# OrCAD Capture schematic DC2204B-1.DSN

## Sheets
1 PAGE1: size C
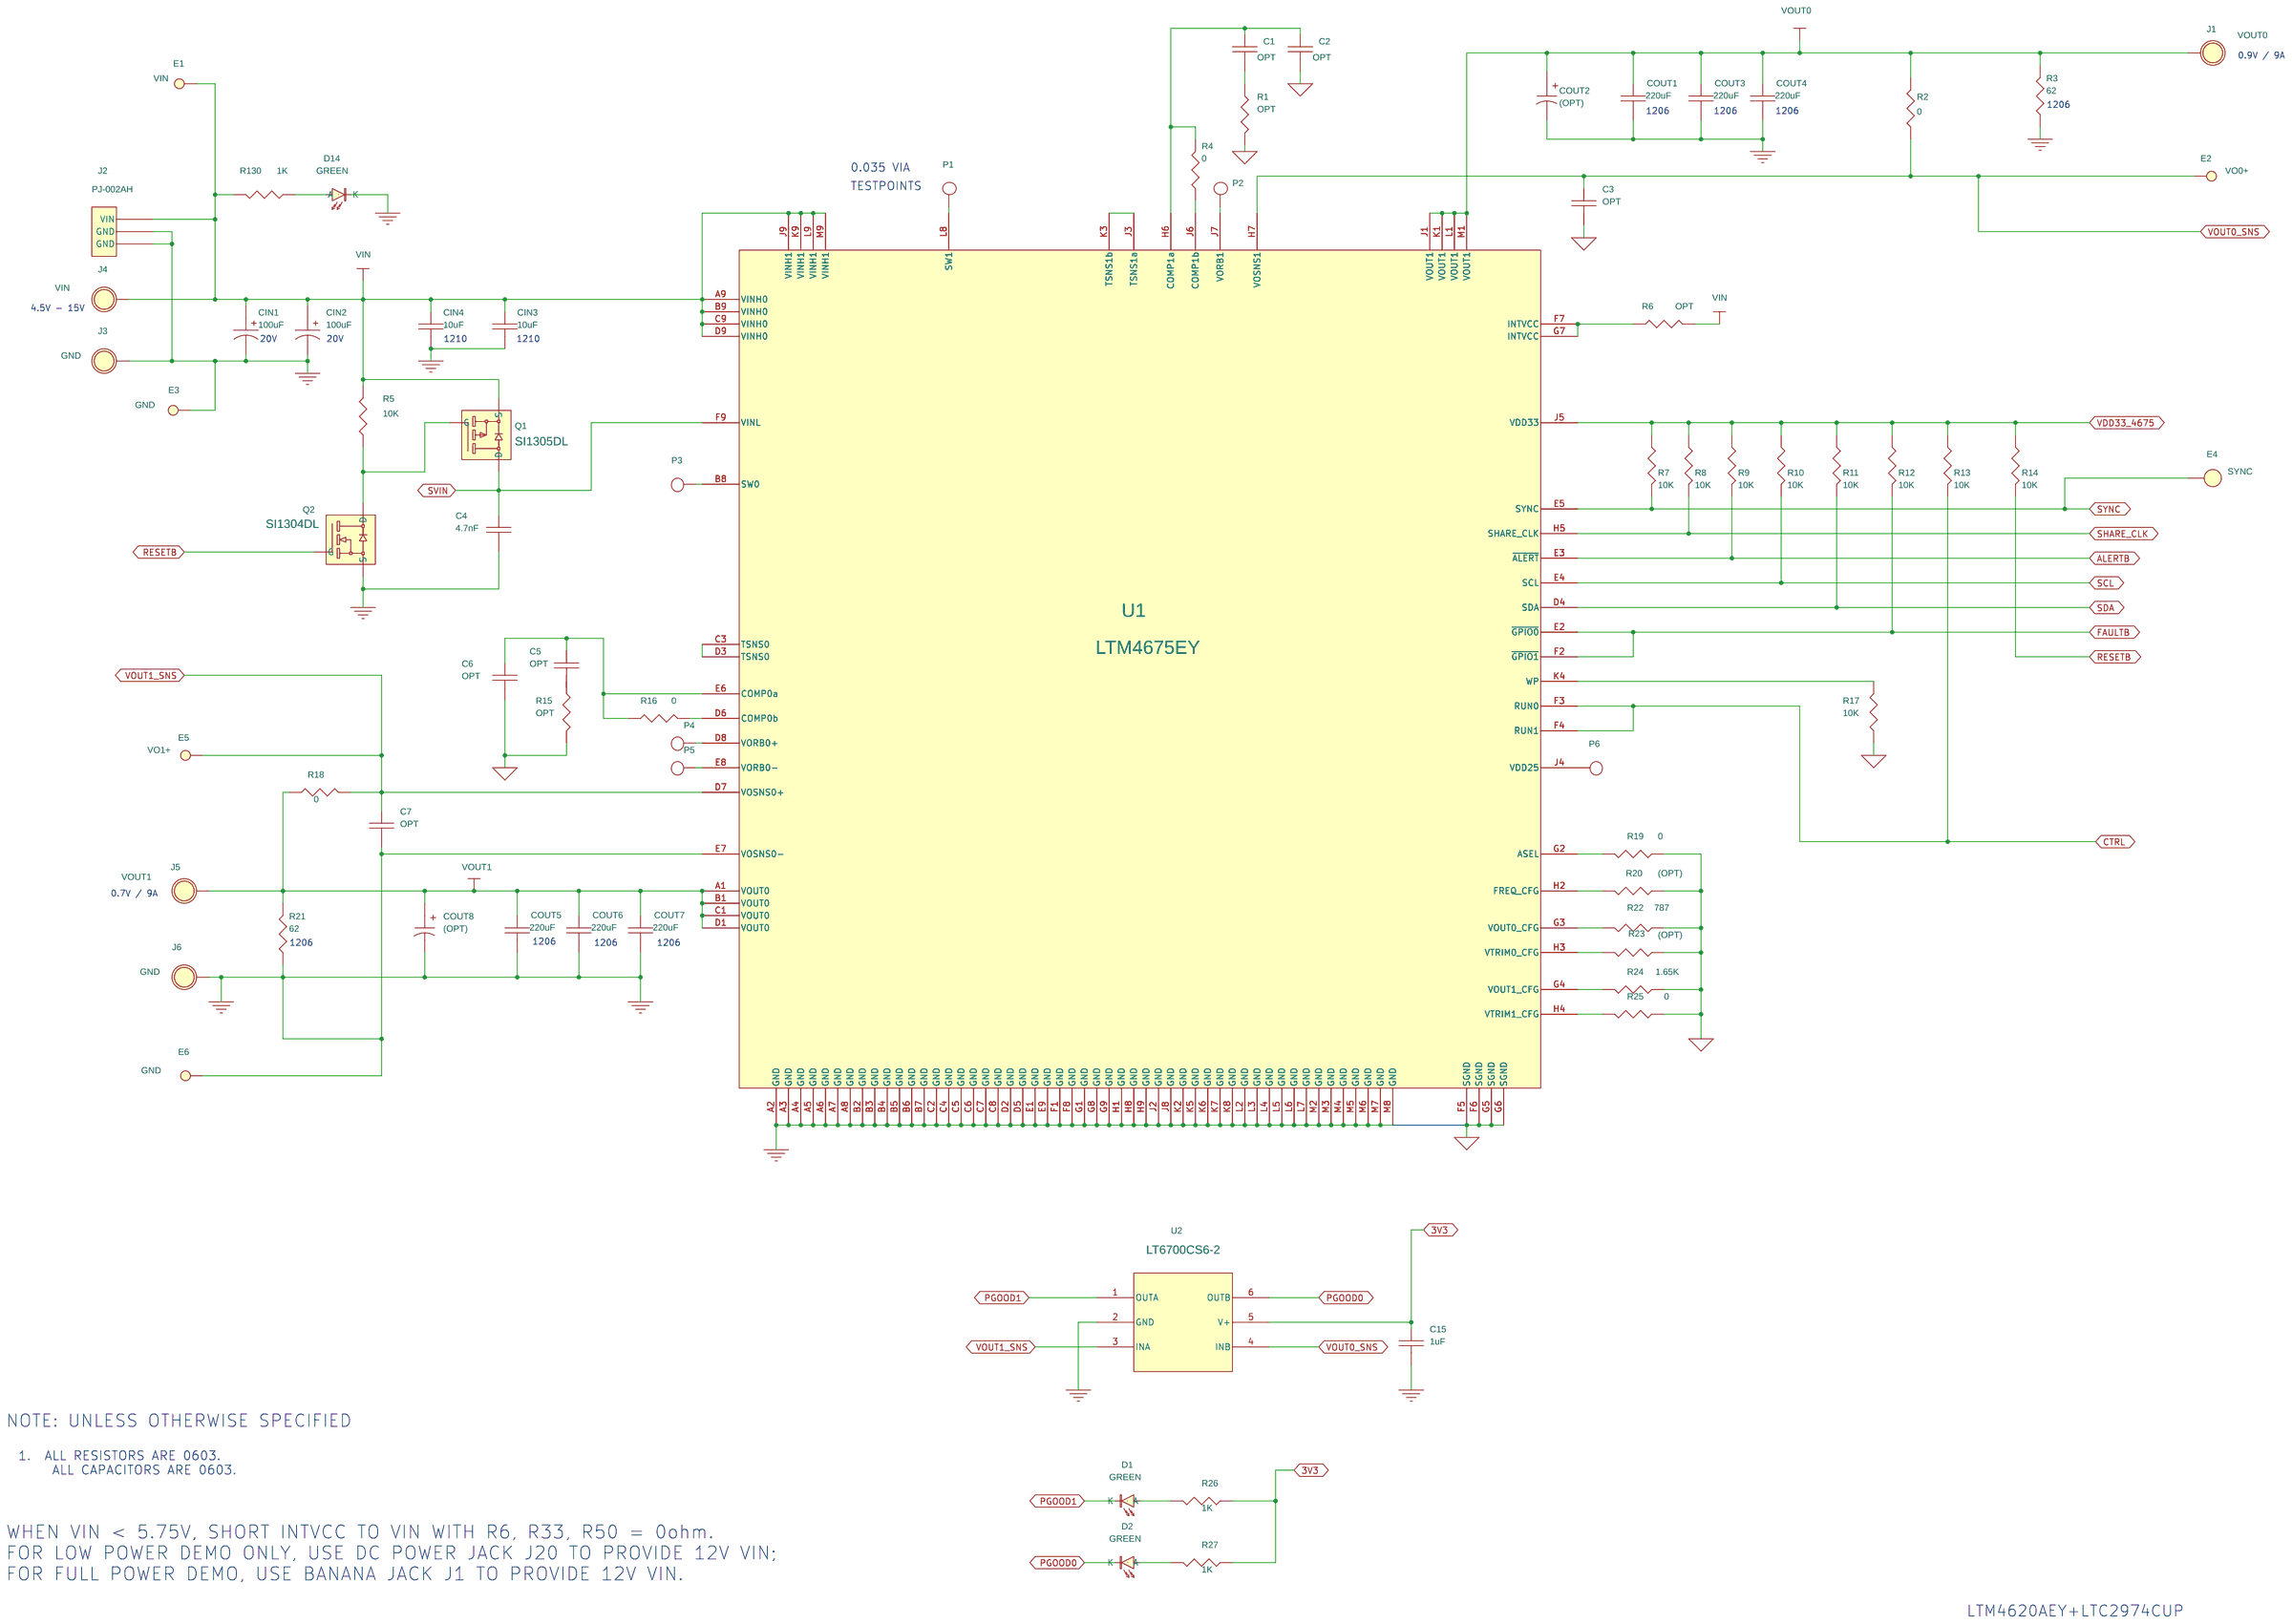
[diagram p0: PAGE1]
2 PAGE2: size C; title: µMODULE POWER STICK WITH POWER SYSTEM MANAGEMENT; rev: 1; company: TM
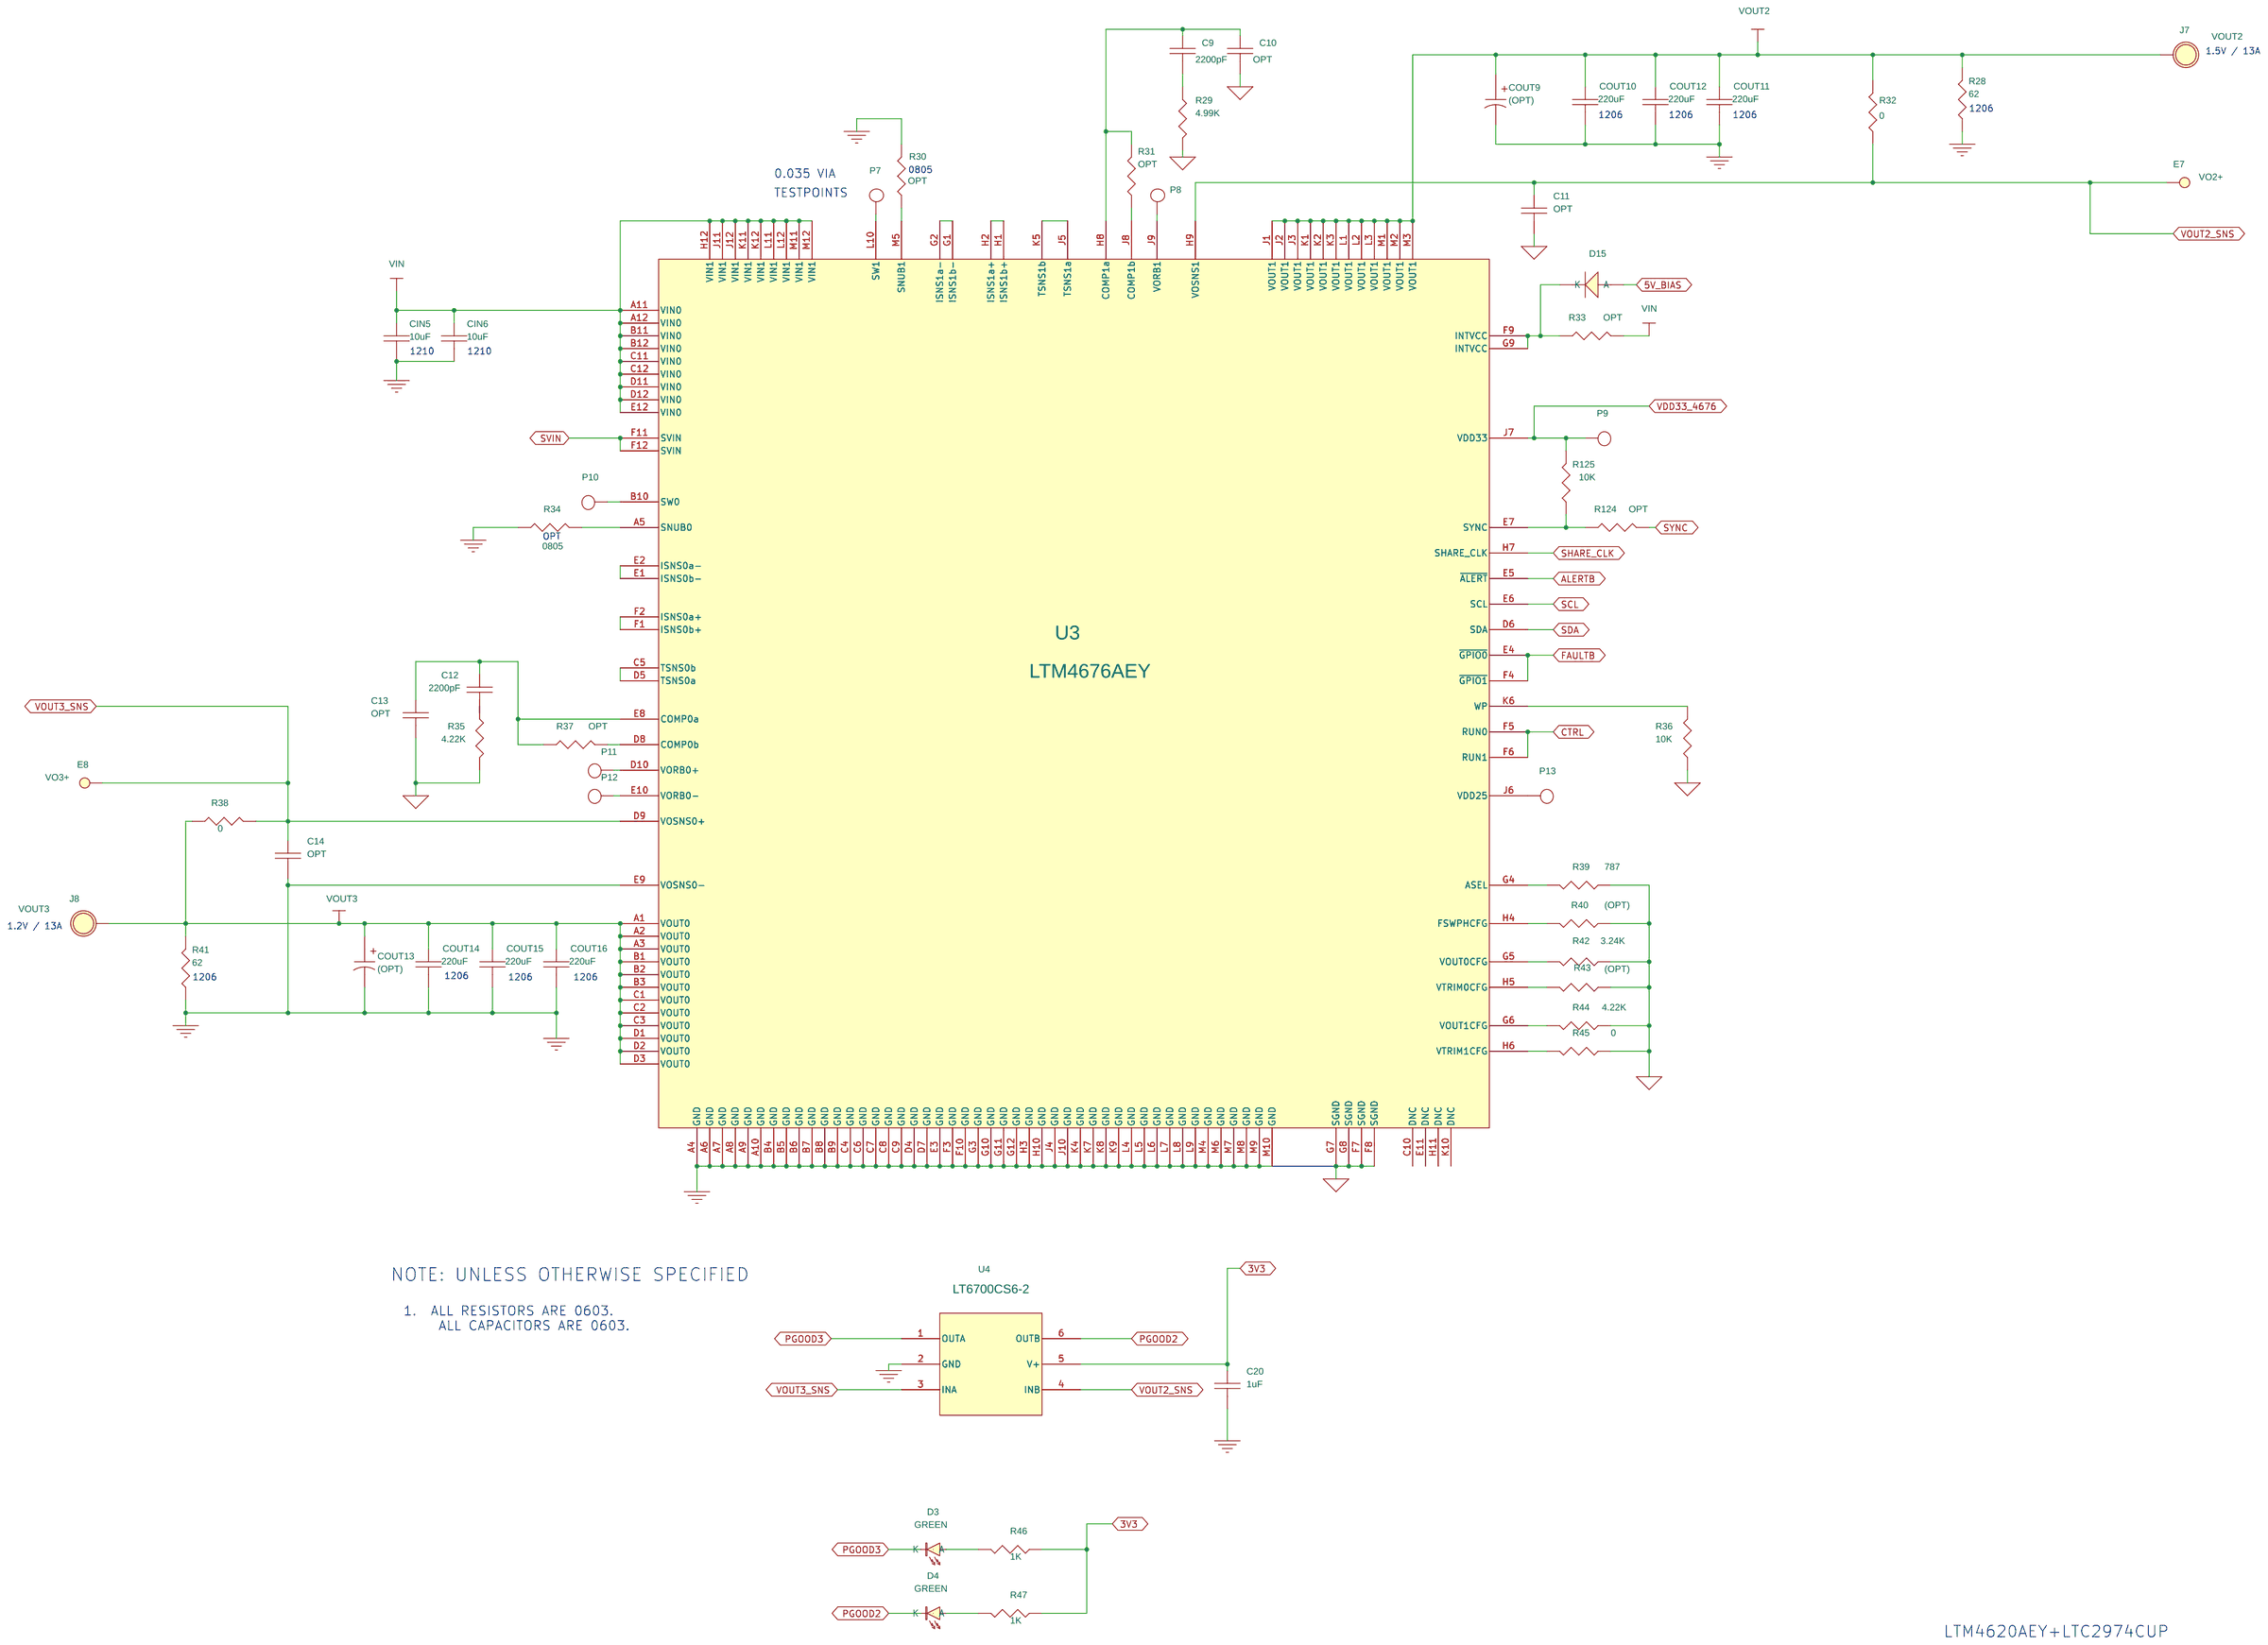
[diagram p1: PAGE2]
3 PAGE3: size C; title: µMODULE POWER STICK WITH POWER SYSTEM MANAGEMENT; rev: 1; company: TM
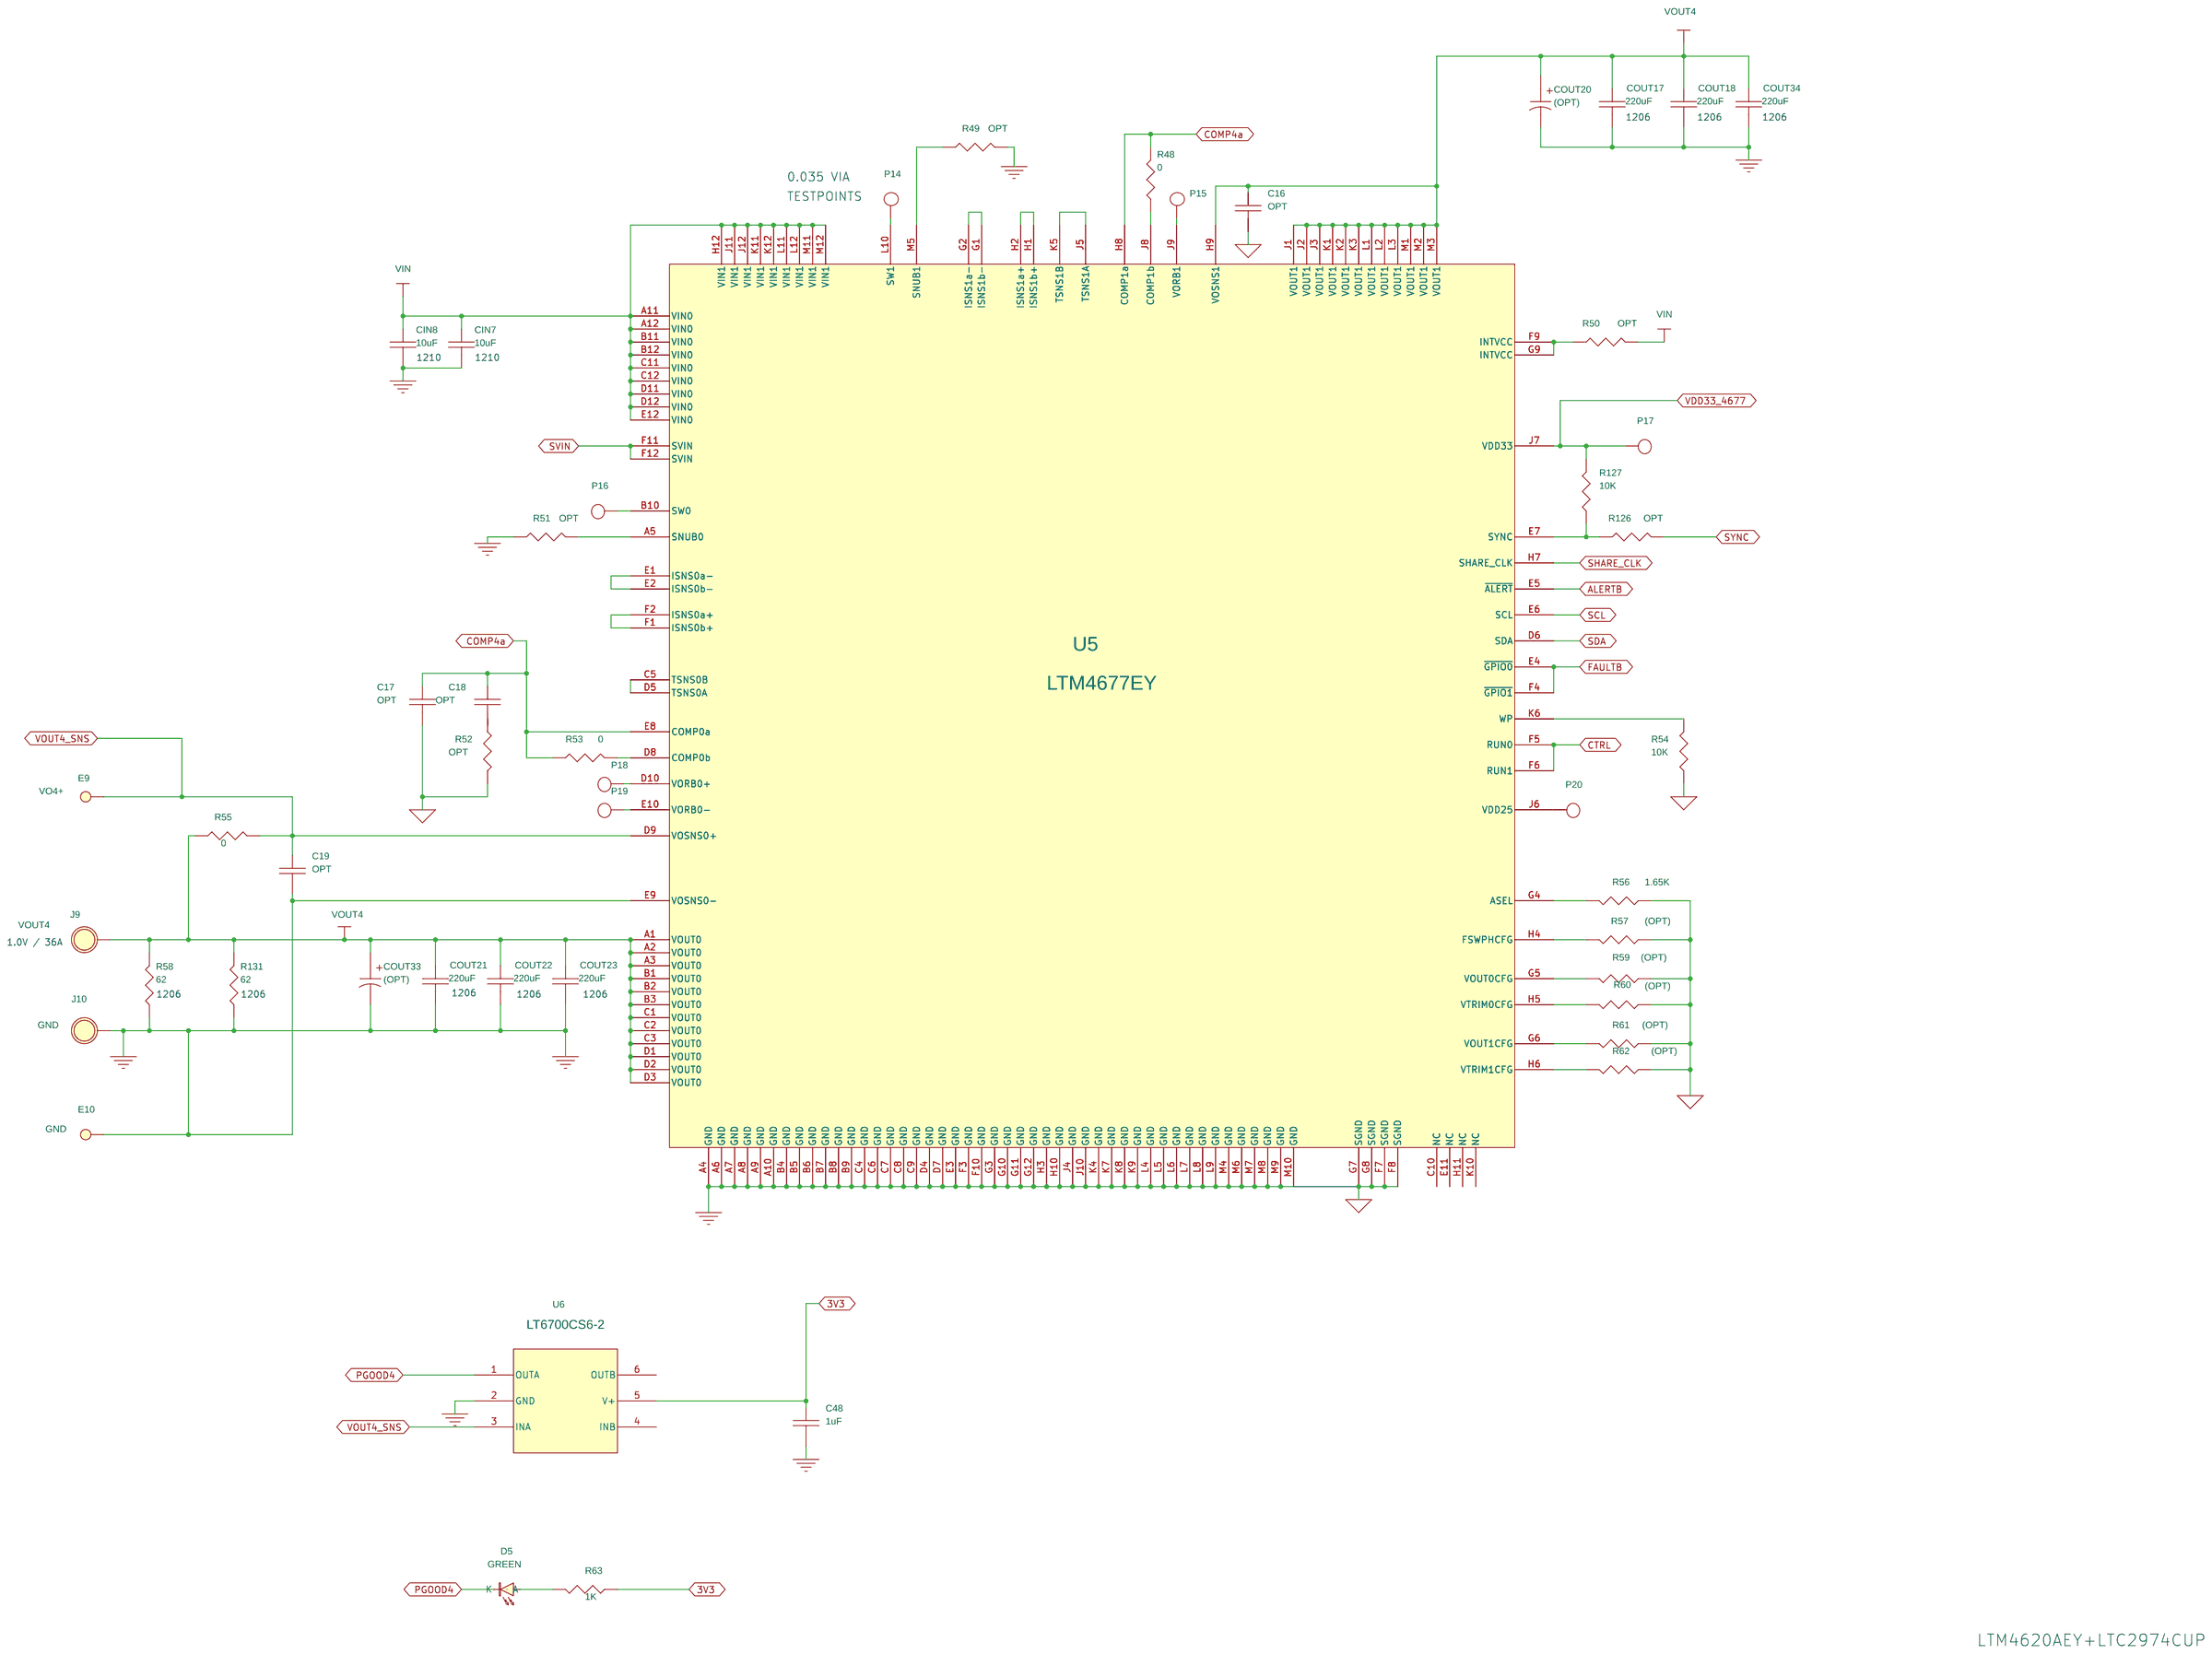
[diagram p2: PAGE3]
4 PAGE4: size Custom; title: µMODULE POWER STICK WITH POWER SYSTEM MANAGEMENT; rev: 1; company: TM
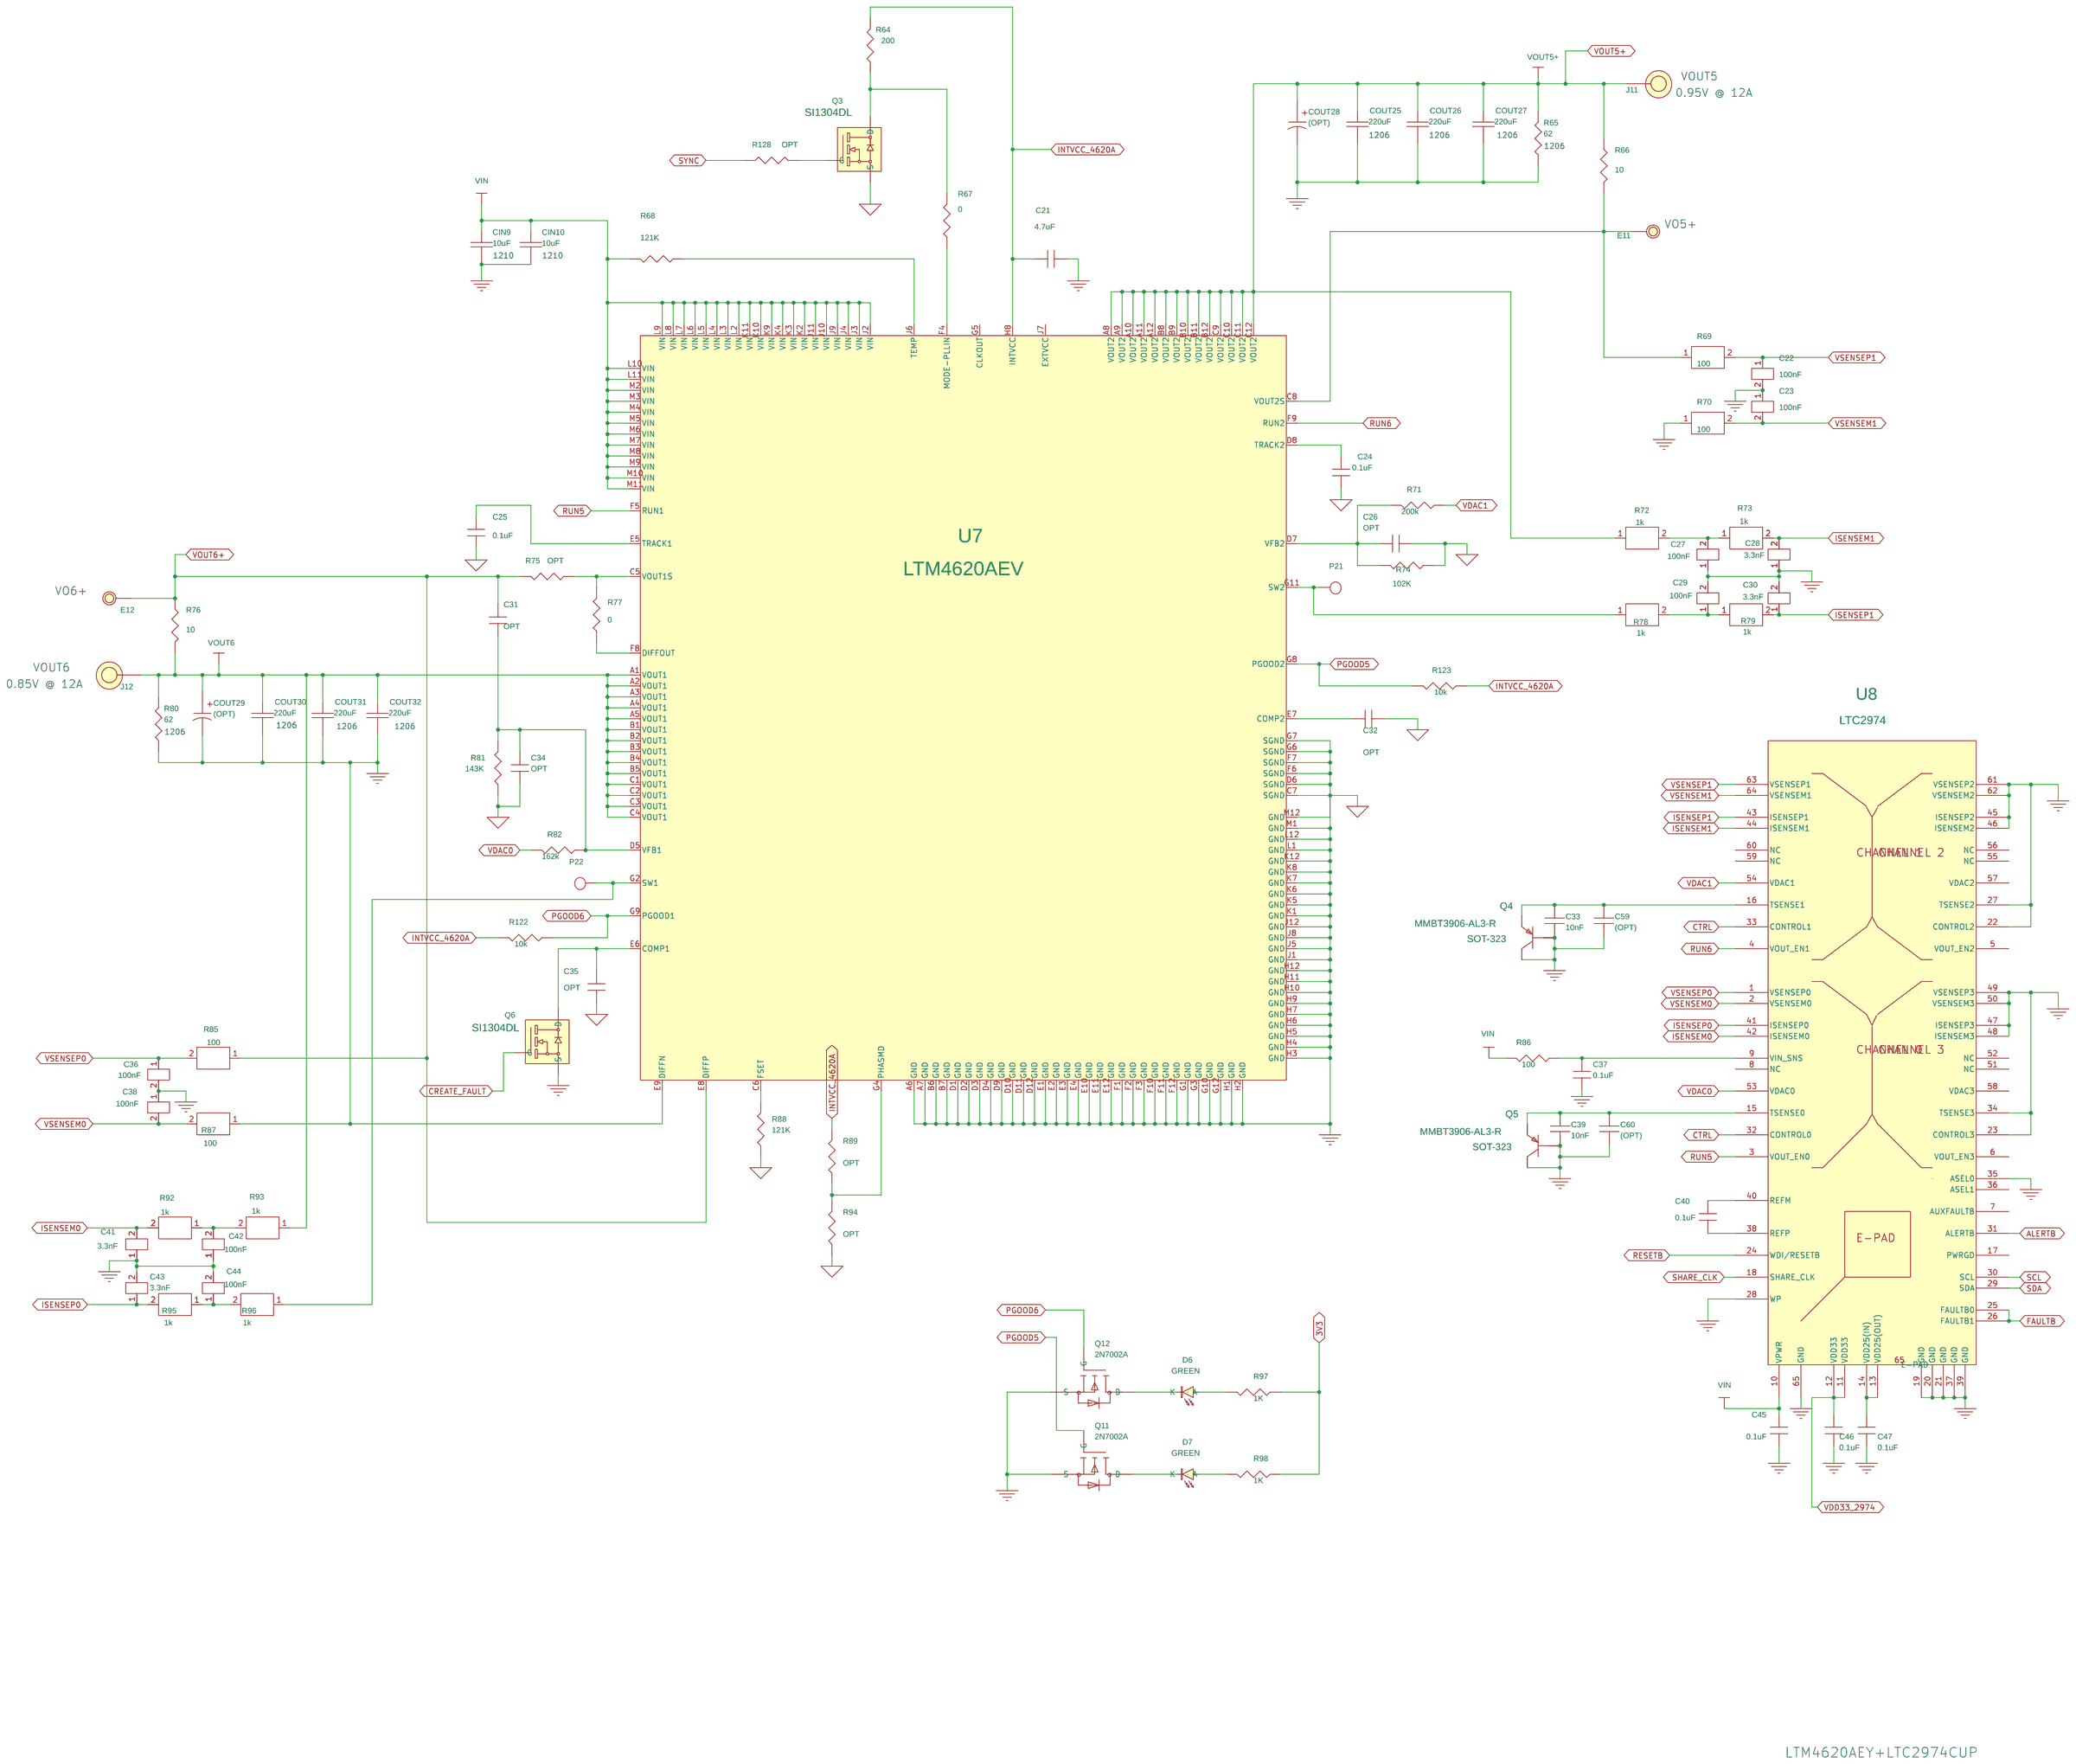
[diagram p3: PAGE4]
5 PAGE5: size C; title: µMODULE POWER STICK WITH POWER SYSTEM MANAGEMENT; rev: 1; company: TM
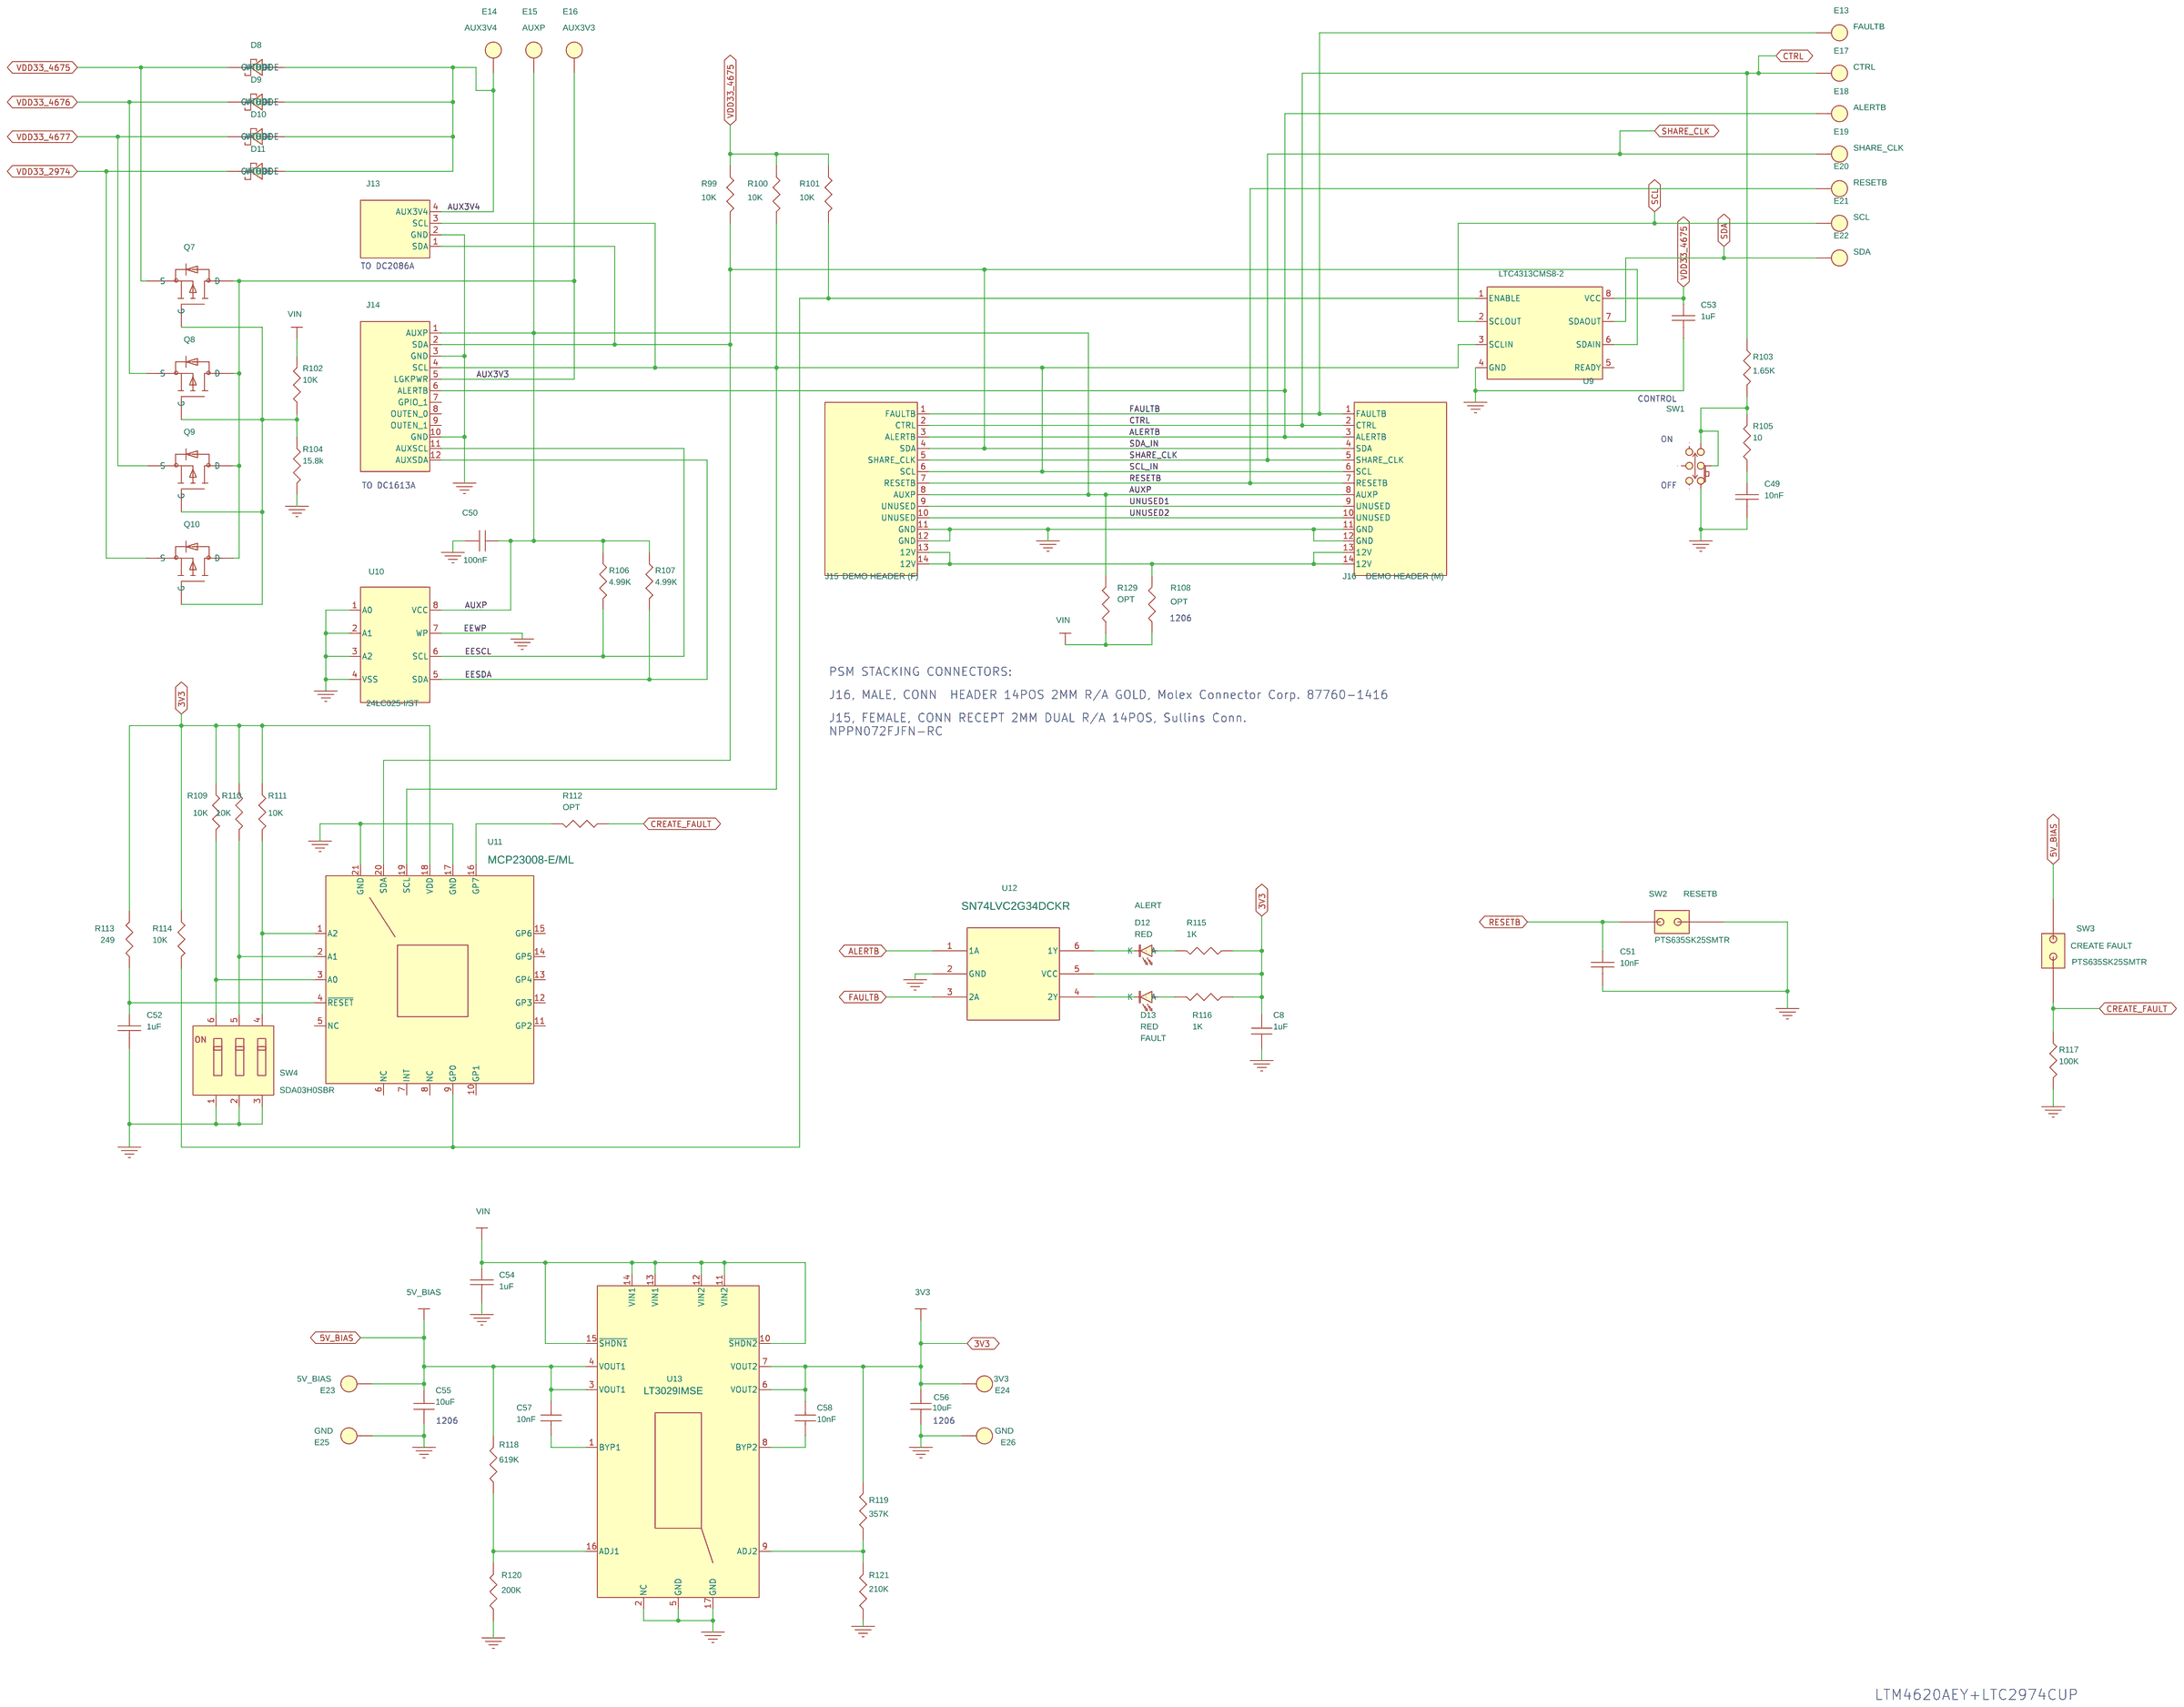
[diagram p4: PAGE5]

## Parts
sheet PAGE1
C1  OPT  [0603]
C2  OPT  [0603]
C3  OPT  [0603]
C4  4.7nF  [0603]
C5  OPT  [0603]
C6  OPT  [0603]
C7  OPT  [0603]
C15  1uF  [0603]
CIN1  100uF  [D3L]
CIN2  100uF  [D3L]
CIN3  10uF  [1210]
CIN4  10uF  [1210]
COUT1  220uF  [1206]
COUT2  (OPT)  [D3L]
COUT3  220uF  [1206]
COUT4  220uF  [1206]
COUT5  220uF  [1206]
COUT6  220uF  [1206]
COUT7  220uF  [1206]
COUT8  (OPT)  [D3L]
D1  GREEN  [LED_0603]
D2  GREEN  [LED_0603]
D14  GREEN  [LED_0603]
E1  TURRETS  [TURRETS]
E2  TURRETS  [TURRETS]
E3  GND  [TURRETS]
E4  SYNC  [TURRETS]
E5  TURRETS  [TURRETS]
E6  TURRETS  [TURRETS]
J1  BANANA SMALL  [KEY-575-4]
J2  PJ-002AH  [PJ-002]
J3  BANANA SMALL  [KEY-575-4]
J4  BANANA SMALL  [KEY-575-4]
J5  BANANA SMALL  [KEY-575-4]
J6  BANANA SMALL  [KEY-575-4]
P1  TURRETS  [PAD]
P2  TURRETS  [PAD]
P3  TURRETS  [PAD]
P4  TURRETS  [PAD]
P5  TURRETS  [PAD]
P6  TURRETS  [PAD]
Q1  SI1305DL  [SOT-323]
Q2  SI1304DL  [SOT-323]
R1  OPT  [0603]
R2  0  [0603]
R3  62  [1206]
R4  0  [0603]
R5  10K  [0603]
R6  OPT  [0603]
R7  10K  [0603]
R8  10K  [0603]
R9  10K  [0603]
R10  10K  [0603]
R11  10K  [0603]
R12  10K  [0603]
R13  10K  [0603]
R14  10K  [0603]
R15  OPT  [0603]
R16  0  [0603]
R17  10K  [0603]
R18  0  [0603]
R19  0  [0603]
R20  (OPT)  [0603]
R21  62  [1206]
R22  787  [0603]
R23  (OPT)  [0603]
R24  0  [0603]
R25  1.65K  [0603]
R26  1K  [0603]
R27  1K  [0603]
R130  1K  [0603]
U1  LTM4675EY  [LTM4675]
U2  LT6700CS6-2  [SOT23-6]
sheet PAGE2
C9  2200pF  [0603]
C10  OPT  [0603]
C11  OPT  [0603]
C12  2200pF  [0603]
C13  OPT  [0603]
C14  OPT  [0603]
C20  1uF  [0603]
CIN5  10uF  [1210]
CIN6  10uF  [1210]
COUT9  (OPT)  [D3L]
COUT10  220uF  [1206]
COUT11  220uF  [1206]
COUT12  220uF  [1206]
COUT13  (OPT)  [D3L]
COUT14  220uF  [1206]
COUT15  220uF  [1206]
COUT16  220uF  [1206]
D3  GREEN  [LED_0603]
D4  GREEN  [LED_0603]
D15  CMDSH-3  [SOD-323]
E7  TURRETS  [TURRETS]
E8  TURRETS  [TURRETS]
J7  BANANA SMALL  [KEY-575-4]
J8  BANANA SMALL  [KEY-575-4]
P7  TURRETS  [PAD]
P8  TURRETS  [PAD]
P9  TURRETS  [PAD]
P10  TURRETS  [PAD]
P11  TURRETS  [PAD]
P12  TURRETS  [PAD]
P13  TURRETS  [PAD]
R28  62  [1206]
R29  4.99K  [0603]
R30  OPT  [0805]
R31  OPT  [0603]
R32  0  [0603]
R33  OPT  [0603]
R34  0805  [0805]
R35  4.22K  [0603]
R36  10K  [0603]
R37  OPT  [0603]
R38  0  [0603]
R39  787  [0603]
R40  (OPT)  [0603]
R41  62  [1206]
R42  3.24K  [0603]
R43  (OPT)  [0603]
R44  0  [0603]
R45  4.22K  [0603]
R46  1K  [0603]
R47  1K  [0603]
R124  OPT  [0603]
R125  10K  [0603]
U3  LTM4676AEY  [LTM4676]
U4  LT6700CS6-2  [SOT23-6]
sheet PAGE3
C16  OPT  [0603]
C17  OPT  [0603]
C18  OPT  [0603]
C19  OPT  [0603]
C48  1uF  [0603]
CIN7  10uF  [1210]
CIN8  10uF  [1210]
COUT17  220uF  [1206]
COUT18  220uF  [1206]
COUT20  (OPT)  [D3L]
COUT21  220uF  [1206]
COUT22  220uF  [1206]
COUT23  220uF  [1206]
COUT33  (OPT)  [D3L]
COUT34  220uF  [1206]
D5  GREEN  [LED_0603]
E9  TURRETS  [TURRETS]
E10  TURRETS  [TURRETS]
J9  BANANA SMALL  [KEY-575-4]
J10  BANANA SMALL  [KEY-575-4]
P14  TURRETS  [PAD]
P15  TURRETS  [PAD]
P16  TURRETS  [PAD]
P17  TURRETS  [PAD]
P18  TURRETS  [PAD]
P19  TURRETS  [PAD]
P20  TURRETS  [PAD]
R48  0  [0603]
R49  OPT  [0805]
R50  OPT  [0603]
R51  OPT  [0805]
R52  OPT  [0603]
R53  0  [0603]
R54  10K  [0603]
R55  0  [0603]
R56  1.65K  [0603]
R57  (OPT)  [0603]
R58  62  [1206]
R59  (OPT)  [0603]
R60  (OPT)  [0603]
R61  (OPT)  [0603]
R62  (OPT)  [0603]
R63  1K  [0603]
R126  OPT  [0603]
R127  10K  [0603]
R131  62  [1206]
U5  LTM4677EY  [LTM4677]
U6  LT6700CS6-2  [SOT23-6]
sheet PAGE4
C21  4.7uF  [0805]
C22  100nF  [0603]
C23  100nF  [0603]
C24  0.1uF  [0603]
C25  0.1uF  [0603]
C26  OPT  [0603]
C27  100nF  [0603]
C28  3.3nF  [0603]
C29  100nF  [0603]
C30  3.3nF  [0603]
C31  OPT  [0603]
C32  OPT  [0603]
C33  10nF  [0603]
C34  OPT  [0603]
C35  OPT  [0603]
C36  100nF  [0603]
C37  0.1uF  [0603]
C38  100nF  [0603]
C39  10nF  [0603]
C40  0.1uF  [0603]
C41  3.3nF  [0603]
C42  100nF  [0603]
C43  3.3nF  [0603]
C44  100nF  [0603]
C45  0.1uF  [0603]
C46  0.1uF  [0603]
C47  0.1uF  [0603]
C59  (OPT)  [0603]
C60  (OPT)  [0603]
CIN9  10uF  [1210]
CIN10  10uF  [1210]
COUT25  220uF  [1206]
COUT26  220uF  [1206]
COUT27  220uF  [1206]
COUT28  (OPT)  [D3L]
COUT29  (OPT)  [D3L]
COUT30  220uF  [1206]
COUT31  220uF  [1206]
COUT32  220uF  [1206]
D6  GREEN  [LED_0603]
D7  GREEN  [LED_0603]
E11  Testpoint  [TURRETS]
E12  Testpoint  [TURRETS]
J11  KEY-575--4  [KEY-575-4]
J12  KEY-575--4  [KEY-575-4]
P21  TURRETS  [PAD]
P22  TURRETS  [PAD]
Q3  SI1304DL  [SOT-323]
Q4  MMBT3906-AL3-R  [SOT-323]
Q5  MMBT3906-AL3-R  [SOT-323]
Q6  SI1304DL  [SOT-323]
Q11  2N7002A  [SOT-23]
Q12  2N7002A  [SOT-23]
R64  200  [0603]
R65  62  [1206]
R66  10  [0603]
R67  0  [0603]
R68  121K  [0603]
R69  100  [0603]
R70  100  [0603]
R71  200k  [0603]
R72  1k  [0603]
R73  1k  [0603]
R74  102K  [0603]
R75  OPT  [0603]
R76  10  [0603]
R77  0  [0603]
R78  1k  [0603]
R79  1k  [0603]
R80  62  [1206]
R81  143K  [0603]
R82  162k  [0603]
R85  100  [0603]
R86  100  [0603]
R87  100  [0603]
R88  121K  [0603]
R89  OPT  [0603]
R92  1k  [0603]
R93  1k  [0603]
R94  OPT  [0603]
R95  1k  [0603]
R96  1k  [0603]
R97  1K  [0603]
R98  1K  [0603]
R122  10k  [0603]
R123  10k  [0603]
R128  OPT  [0603]
U7  LTM4620AEV  [LTM4620]
U8  LTC2974  [QFN_64_9MMX9MM_UP]
sheet PAGE5
C8  1uF  [0603]
C49  10nF  [0603]
C50  100nF  [0603]
C51  10nF  [0603]
C52  1uF  [0603]
C53  1uF  [0603]
C54  1uF  [1206]
C55  10uF  [1206]
C56  10uF  [1206]
C57  10nF  [0603]
C58  10nF  [0603]
D8  DIODE SCHOTTKY  [PMEG2005AEL]
D9  DIODE SCHOTTKY  [PMEG2005AEL]
D10  DIODE SCHOTTKY  [PMEG2005AEL]
D11  DIODE SCHOTTKY  [PMEG2005AEL]
D12  RED  [LED_0603]
D13  RED  [LED_0603]
E13  FAULTB  [TURRETS]
E14  AUX3V4  [TURRETS]
E15  AUXP  [TURRETS]
E16  AUX3V3  [TURRETS]
E17  CTRL  [TURRETS]
E18  ALERTB  [TURRETS]
E19  SHARE_CLK  [TURRETS]
E20  RESETB  [TURRETS]
E21  SCL  [TURRETS]
E22  SDA  [TURRETS]
E23  5V_BIAS  [TURRETS]
E24  3V3  [TURRETS]
E25  GND  [TURRETS]
E26  GND  [TURRETS]
J13  HD2X6-079-PMBUS_0  [DF3A-4P-2DSA]
J14  HD2X6-079  [HD2X6-079-MOLEX]
J15  DEMO HEADER (F)  [NPPN072FJFN-RC]
J16  DEMO HEADER (M)  [NPPN072FJFN]
Q7  DMP3130L  [SOT-23]
Q8  DMP3130L  [SOT-23]
Q9  DMP3130L  [SOT-23]
Q10  DMP3130L  [SOT-23]
R99  10K  [0603]
R100  10K  [0603]
R101  10K  [0603]
R102  10K  [0603]
R103  1.65K  [0603]
R104  15.8k  [0603]
R105  10  [0603]
R106  4.99K  [0603]
R107  4.99K  [0603]
R108  OPT  [1206]
R109  10K  [0603]
R110  10K  [0603]
R111  10K  [0603]
R112  OPT  [0603]
R113  249  [0603]
R114  10K  [0603]
R115  1K  [0603]
R116  1K  [0603]
R117  100K  [0603]
R118  619K  [0603]
R119  357K  [0603]
R120  200K  [0603]
R121  210K  [0603]
R129  OPT  [0603]
SW1  JP3X1/079\NO\12  [JS202011]
SW2  RESETB  [SMT_25]
SW3  CREATE FAULT  [SMT_25]
SW4  SDA03H0SBR  [SDA03H0SB]
U9  LTC4313CMS8-2  [MSOP_8_MS8]
U10  24LC025-I/ST  [TSSOP-8_4.4MM]
U11  MCP23008-E/ML  [mcp23008]
U12  SN74LVC2G34DCKR  [SOT-DCK]
U13  LT3029IMSE  [MSOP_16_MSE]

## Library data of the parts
C1-C7 C9-C14 C16-C19 = CAP0603_1: Component: cap; Manufacturer: TDK; Manufacturer P/N: C1608C0G1H102J; Tolerance: 5%; Type: cer 0603; Vendor: Digikey; Vendor P/N: 445-1293-1-ND; Volts/Amps/Watts: 50V
C15 C20 C48 = CAP0603_1: Component: cap; Manufacturer: TDK; Manufacturer P/N: C1608C0G1H102J; Tolerance: 5%; Type: cer 0603; Vendor: Digikey; Vendor P/N: 445-1293-1-ND; Volts/Amps/Watts: 10V
CIN1 CIN2 = CAPR12X5_0: Component: cap; Manufacturer: SANYO; Tolerance: 20%; Type: OS-CON; Volts/Amps/Watts: 16V
CIN3-CIN10 = CAP1210_1: Component: cap; Manufacturer: Taiyo Yuden; Manufacturer P/N: GMK325BJ106KN-T; Tolerance: 10%; Type: cer 1210; Vendor: Digikey; Vendor P/N: 587-1439-1-ND; Volts/Amps/Watts: 35V
COUT1 COUT3-COUT7 COUT10-COUT12 COUT14-COUT18 COUT21-COUT23 COUT25-COUT27 COUT30-COUT32 COUT34 = CAP0603_1: Component: cap; Manufacturer: MURATA; Manufacturer P/N: GRM31CR60G227M; Part Type: CAP1206; Tolerance: 20%; Type: cer 1206 X5R; Vendor: Digikey; Vendor P/N: 445-1437-1-ND; Volts/Amps/Watts: 4v
COUT2 COUT8 COUT9 COUT13 COUT20 COUT28 COUT29 COUT33 = 4TPE470MCL
D1-D7 D14 = DIODE-LED_2: Manufacturer: PANASONIC; Manufacturer P/N: LN1371SGTRP
E1 = TURRETS_1: Component: tp; Label: VIN; Manufacturer: Keystone; Manufacturer P/N: 1593-2; Vendor: Digikey; Vendor P/N: 1593-2K-ND
E2 = TURRETS_1: Component: tp; Label: VO0+; Vendor: Digikey; Vendor P/N: 1593-2K-ND
E3 = TURRETS_1: Component: tp; Manufacturer: Keystone; Manufacturer P/N: 1593-2; Vendor: Digikey; Vendor P/N: 1593-2K-ND
E4 E13-E26 = E_0: TURRET; Part Number: MILL MAX 2501-2-00-80-00-00-07-0
E5 = TURRETS_1: Component: tp; Label: VO1+; Vendor: Digikey; Vendor P/N: 1593-2K-ND
E6 E10 = TURRETS_1: Component: tp; Label: GND; Vendor: Digikey; Vendor P/N: 1593-2K-ND
J1 = BANANA_SMALL_0: Component: conn; Label: VOUT0
J2 = CON3_0
J3 J6 J10 = BANANA_SMALL_0: Component: conn; Label: GND
J4 = BANANA_SMALL_0: Component: conn; Label: VIN
J5 = BANANA_SMALL_0: Component: conn; Label: VOUT1
P1-P22 = PAD_2: Component: tp; Label: <Label>; Vendor: Digikey; Vendor P/N: 1593-2K-ND
Q1 = MOSFET_0: 5th Part Field: SiR422DP
Q2 Q3 Q6 = MOSFET_1: 5th Part Field: SiR422DP
R1 R15 R29 R35 R52 R64 = RES0603_9: Component: res; Label: <label>; Manufacturer: Panasonic; Manufacturer P/N: ERJ-3EKF5901V; Tolerance: 1%; Vendor: Digikey; Vendor P/N: P5.90KHCT-ND; Volts/Amps/Watts: 0.1W
R2 R4 R5 R16 R31 R32 R37 R48 R53 R130 = RES0603_9: Manufacturer: Rohm; Manufacturer P/N: RHM0.0GCT-ND; Tolerance: 5%; Vendor: Digikey; Vendor P/N: RHM0.0GCT-ND; Volts/Amps/Watts: 0.1W
R3 R21 R28 R41 R58 R65 R80 R131 = RES0603_5: Label: 1W; Manufacturer: VISHAY; Manufacturer P/N: CRCW1206470RJNEA; Tolerance: 5%; Vendor: Digikey; Vendor P/N: 541-30XCT-ND; Volts/Amps/Watts: 0.25W
R6 R33 R50 R124-R128 = RES0603_9: Label: OPT 0; Manufacturer: Rohm; Manufacturer P/N: RHM0.0GCT-ND; Vendor: Digikey
R7-R14 R17 R23 R24 R26 R27 R36 R43 R44 R46 R47 R54 R60 R61 R63 R97-R101 R109-R111 R114 = RES0603_9: Manufacturer: ROHM; Manufacturer P/N: MCR03EZPFX1002; Vendor: Digikey; Vendor P/N: RHM10.0KHCT-ND; Volts/Amps/Watts: 0.1W
R18 R38 R55 = RES0603_9: Manufacturer: Rohm; Manufacturer P/N: MCR03EZPFX1000; Vendor: Digikey; Vendor P/N: RHM100HCT-ND; Volts/Amps/Watts: 0.1W
R19 R20 R39 R40 R56 R57 = RES0603_9: Manufacturer: Panasonic; Manufacturer P/N: ERJ-3EKF2002V; Vendor: Digikey; Vendor P/N: P20.0KHCT-ND; Volts/Amps/Watts: 0.1W
R22 R42 R59 = RES0603_9: Manufacturer: Panasonic; Manufacturer P/N: ERJ-3EKF1000V; Vendor: Digikey; Vendor P/N: P100HCT-ND; Volts/Amps/Watts: 0.1W
R25 R45 R62 = RES0603_9: Manufacturer: Panasonic; Manufacturer P/N: ERJ-3EKF1021V; Vendor: Digikey; Vendor P/N: P1.02KHCT-ND; Volts/Amps/Watts: 0.1W
U1 = LTC3880-M0001_21: Component: IC; Manufacturer: LTC; Manufacturer P/N: LTC3880_M0001; Vendor: LTC; Vendor P/N: LTC3880_M0001
U2 U4 U6 = LTC3429ES6_2
D15 = CMDD4448: Component: diode; Manufacturer: Central; Manufacturer P/N: CMDSH-3TR; Type: Schottky; Vendor: Mouser; Vendor P/N: 610-CMDSH-3; Volts/Amps/Watts: 30V 100mA
E7 = TURRETS_1: Component: tp; Label: VO2+; Vendor: Digikey; Vendor P/N: 1593-2K-ND
E8 = TURRETS_1: Component: tp; Label: VO3+; Vendor: Digikey; Vendor P/N: 1593-2K-ND
J7 = BANANA_SMALL_0: Component: conn; Label: VOUT2
J8 = BANANA_SMALL_0: Component: conn; Label: VOUT3
R30 R34 = RES0603_9
U3 = LTC3880-M0001_33: Component: IC; Manufacturer: LTC; Manufacturer P/N: LTC3880_M0001; Vendor: LTC; Vendor P/N: LTC3880_M0001
E9 = TURRETS_1: Component: tp; Label: VO4+; Vendor: Digikey; Vendor P/N: 1593-2K-ND
J9 = BANANA_SMALL_0: Component: conn; Label: VOUT4
R49 R51 = RES0603_3
U5 = LTC3880-M0001_22: Component: IC; Manufacturer: LTC; Manufacturer P/N: LTC3880_M0001; Vendor: LTC; Vendor P/N: LTC3880_M0001
C21 C24 C25 = CAP1206: 1ST PART FIELD: 25V; 2ND PART FIELD: 0805-1206
C22 C23 C27 C29 C36 C38 C42 = CAP_0603_0.1µF_±10%,_25V-REEL: Alternate Vendor Price: $0.00; Comments / Special Instructions: Required Component!
C26 C31 C32 C34 C35 C37 C40 C45-C47 = CAP1206: 1ST PART FIELD: 6.3V; 2ND PART FIELD: 0805-1206
C28 C30 C41 C43 = CAP_0603_4: Alternate Vendor Price: $0.00
C33 C39 C59 C60 = CAP_NP: CAP, 0603 10nF 10% 25V X7R; Part Number: AVX 06033C103KAT2A
C44 = CAP_0603_0.1µF_±10%,_25V-REEL: Alternate Vendor Price: $0.00; Comments / Special Instructions: Required Component!; Part Type: 0603_(160
E11 E12 = MillMax-2501
J11 J12 = KEY-575--4_1
Q4 Q5 = MMBT3906_SOT_0: XSTR, PNP GENERAL PURPOSE; Part Number: DIODES INC. MMST3906-7-F
Q11 Q12 = TRANSISTOR_0: XSTR, N-CHANNEL DMOS FET
R66-R68 R71 R74-R77 R81 R82 R86 R88 R89 R94 R122 R123 = AAC-0603
R69 R70 R85 R87 = RES_0603_1: Alternate Vendor Price: $0.00; Comments / Special Instructions: Required Component!
R72 R73 R78 R79 R92 R93 R95 R96 = RES_0603_0.00K_±1%,_1_10W-REEL: Alternate Vendor Price: $0.00
U7 = LTM4620_0
U8 = LTC2974_9x9_QFN_UP64_0: LTC2974 Package Part; Alternate Vendor: N/A; Alternate Vendor Part Number: N/A; Alternate Vendor Price: $0.00; Datasheet Location: \\Mcnally2\Datasheets\N/A; Demo Board Manufacturer: Linear Technology; Demo Board Quantity Available In Stock: N/A; Digikey Link: N/A; Digikey Part Number: N/A; Electrical Symbol Approved: Yes; Electrical Symbol Check Against Datasheet: Sean McNally; Electrical Symbol Drawn: Sean McNally; Electrical Symbol Drawn Date: Wednesday, December 08, 2010; Electrical Symbol Rev Code: 0; Electrical Symbol Revision: 0; Engineer's Qty: N/A; Garrett Part Number: N/A; Label1: N/A; Label2: N/A; Label3: N/A; Last Update: Wednesday, December 08, 2010; Manufacturer: Linear Technology; Order Status: N/A; Other Names: N/A; Packaging: N/A; Part Type: 9X9UP; Price Each: $0.00; Qty In House: N/A; Quantity Available: N/A; RoHS Replacement: N/A; RoHS Status: Lead free / RoHS Compliant; Standard Package: N/A; Tolerance: N/A; Volts/Amps: N/A; Volts/Watts: N/A
C8 C50 = CAP_NP: CAP, 0603 100nF 20% 16V X7R; Part Number: AVX 0603YC104MAT2A
C49 C51-C53 = CAP0603_2: Component: cap; Manufacturer: TDK; Manufacturer P/N: C1608C0G1H102J; Tolerance: 5%; Type: cer 0603; Vendor: Digikey; Volts/Amps/Watts: 25V
C54 = CAP1206_1: Manufacturer: AVX; Manufacturer P/N: 12063C105KAT2A; Tolerance: 10%; Type: cer 1206 X7R; Vendor: Digikey; Vendor P/N: 478-1567-1-ND; Volts/Amps/Watts: 25V
C55 C56 = CAP_NP: Tolerance: X5R
C57 C58 = CAP_NP: CAP, 0402 0.01uF 10% 25V X7R; FIELD1: 0402; Tolerance: X7R
D8-D11 = DIODE_SCHOTTKY_0
D12 = DIODE-LED_0: Label: ALERT; Manufacturer: PANASONIC
D13 = DIODE-LED_1: Label: FAULT; Manufacturer: PANASONIC
J13 = HD2X6-079-PMBUS_4: HEADER, 4PIN 2mm STR DL; Manufacturer: Hirose; Type: header 4POS 2MM VERT
J14 = HD2X6-079-PMBUS_2: HEADER, 12PIN 2mm STR DL; Label: DC1427A HEADER; Manufacturer: MOLEX; Manufacturer P/N: 87831-1220; Part Number: FCI 98414-G06-12ULF; Type: header 12POS 2MM VERT; Vendor: Digikey; Vendor P/N: WM18561-ND
J15 = PMBUS_HEADER20_3: HEADER, 20PIN DUAL ROW R/A; Component: con; Manufacturer: Mill Max; Manufacturer P/N: 802-40-020-20-0001; Part Number: MILL MAX 802-40-020-20-0001; Type: header RA 20 dual row; Vendor: LTC; Vendor P/N: 802-40-020-20-001
J16 = PMBUS_CONNECTOR20_3: CONN, SOCKET 20PIN  DUAL ROW R/A; Component: con; Manufacturer: Mill Max; Manufacturer P/N: 803-93-020-20-001; Part Number: MILL MAX 803-93-020-20-001; Type: conn  RA 20 dual row; Vendor: LTC; Vendor P/N: 803-93-020-20-001
Q7-Q10 = P-MOSFET: XSTR, N-CHANNEL DMOS FET; Part Number: DIODE DMP3130L
R102 = RES0603_11: RES, 0603 10K OHMS 5% 1/10W; Part Number: VISHAY CRCW060310K0JNEA
R103 = RES0603_1: Manufacturer: ROHM; Manufacturer P/N: MCR03EZPFX1002; Vendor: Digikey; Vendor P/N: RHM10.0KHCT-ND; Volts/Amps/Watts: 0.1W
R104 = RES0603_11: RES, 0603 15.8K OHMS 1% 1/10W; Part Number: VISHAY CRCW060315K8FKEA
R105 R113 = RES0603_1: Manufacturer: Rohm; Manufacturer P/N: RHM0.0GCT-ND; Tolerance: 5%; Vendor: Digikey; Vendor P/N: RHM0.0GCT-ND; Volts/Amps/Watts: 0.1W
R106 R107 R117 = RES0603_0: RES, 0603 4.99K OHMS 1% 1/10W; Manufacturer: ROHM; Manufacturer P/N: MCR03EZPFX4991; Part Number: VISHAY CRCW06034K99FKEA; Vendor: Digikey; Vendor P/N: RHM4.99KHCT-ND; Volts/Amps/Watts: 0.1w
R108 R129 = RES0603_3: RES, 0603 OPTION; Label: OPT 0; Manufacturer: Rohm; Manufacturer P/N: RHM0.0GCT-ND; Part Number: OPTION; Tolerance: 5%; Vendor: Digikey; Vendor P/N: RHM0.0GCT-ND; Volts/Amps/Watts: 0.1W
R112 R115 R116 = RES0603_9: Label: OPT 0; Manufacturer: Rohm; Manufacturer P/N: RHM0.0GCT-ND; Tolerance: 5%; Vendor: Digikey; Vendor P/N: RHM0.0GCT-ND; Volts/Amps/Watts: 0.1W
R118-R121 = RESISTOR
SW1 = JP3X1_079_NO_12_3
SW2 SW3 = B2S: VENDOR P/N: PTS635SK25SMTR
SW4 = SW_1
U9 = LT1129CS8-3_0.3: Type: 2-WIRE BUS BUFFER
U10 = 24LC025-I_SN: IC, 24LC05-I/ST; Part Number: MICROCHIP 24LC025-I/ST
U11 = LTC3524EUF_18
U12 = LTC3429ES6_3: 4th Part Field: TI
U13 = LT3023EDD-10DFN_0

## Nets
3V3: C8.1 C15.1 C20.1 C48.1 C56.1 C58.1 E24.1(A) R26.1 R27.1 R46.1 R47.1 R63.1 R97.1 R98.1 R109.1 R110.1 R111.1 R113.2 R114.1 R115.1 R116.1 R119.1 U2.5(V+) U4.5(V+) U6.5(V+) U11.18(VDD) U12.5(VCC) U13.6(VOUT2) U13.7(VOUT2)
5V_BIAS: C55.1 C57.1 D15.2(A) E23.1(A) R118.1 SW3.1 U13.3(VOUT1) U13.4(VOUT1)
GND_POWER: C4.2 C7.2 C8.2 C14.2 C15.2 C19.2 C20.2 C21.2 C22.2 C23.1 C27.1 C28.1 C29.2 C30.2 C33.2 C36.2 C37.2 C38.1 C39.2 C41.1 C42.1 C43.2 C44.2 C45.2 C46.2 C47.2 C48.2 C49.2 C50.2 C51.2 C52.2 C53.2 C54.2 C55.2 C56.2 C59.2 C60.2 CIN1.2 CIN2.2 CIN3.2 CIN4.2 CIN5.2 CIN6.2 CIN7.2 CIN8.2 CIN9.2 CIN10.2 COUT1.2 COUT2.2 COUT3.2 COUT4.2 COUT5.2 COUT6.2 COUT7.2 COUT8.2 COUT9.2 COUT10.2 COUT11.2 COUT12.2 COUT13.2 COUT14.2 COUT15.2 COUT16.2 COUT17.2 COUT18.2 COUT20.2 COUT21.2 COUT22.2 COUT23.2 COUT25.2 COUT26.2 COUT27.2 COUT28.2 COUT29.2 COUT30.2 COUT31.2 COUT32.2 COUT33.2 COUT34.2 D14.2(K) E3.1(TP) E6.1(TP) E10.1(TP) E25.1(A) E26.1(A) J2.2(GND) J2.3(GND) J3.1(TP) J6.1(TP) J10.1(TP) J13.2(GND) J14.3(GND) J14.10(GND) J15.11(GND) J15.12(GND) J16.11(GND) J16.12(GND) Q2.2(S) Q4.1(B) Q4.3(C) Q5.1(B) Q5.3(C) Q6.2(S) Q11.2(S) Q12.2(S) R3.1 R21.1 R28.1 R30.2 R34.2 R41.1 R49.2 R51.1 R58.1 R65.1 R70.1 R80.1 R87.1 R104.2 R117.2 R120.2 R121.2 R131.1 SW1.3 SW2.2 SW4.1 SW4.2 SW4.3 U1.A2(GND) U1.A3(GND) U1.A4(GND) U1.A5(GND) U1.A6(GND) U1.A7(GND) U1.A8(GND) U1.B2(GND) U1.B3(GND) U1.B4(GND) U1.B5(GND) U1.B6(GND) U1.B7(GND) U1.C2(GND) U1.C4(GND) U1.C5(GND) U1.C6(GND) U1.C7(GND) U1.C8(GND) U1.D2(GND) U1.D5(GND) U1.E1(GND) U1.E7(VOSNS0-) U1.E9(GND) U1.F1(GND) U1.F8(GND) U1.G1(GND) U1.G8(GND) U1.G9(GND) U1.H1(GND) U1.H8(GND) U1.H9(GND) U1.J2(GND) U1.J8(GND) U1.K2(GND) U1.K5(GND) U1.K6(GND) U1.K7(GND) U1.K8(GND) U1.L2(GND) U1.L3(GND) U1.L4(GND) U1.L5(GND) U1.L6(GND) U1.L7(GND) U1.M2(GND) U1.M3(GND) U1.M4(GND) U1.M5(GND) U1.M6(GND) U1.M7(GND) U1.M8(GND) U2.2(GND) U3.A4(GND) U3.A6(GND) U3.A7(GND) U3.A8(GND) U3.A9(GND) U3.A10(GND) U3.B4(GND) U3.B5(GND) U3.B6(GND) U3.B7(GND) U3.B8(GND) U3.B9(GND) U3.C4(GND) U3.C6(GND) U3.C7(GND) U3.C8(GND) U3.C9(GND) U3.D4(GND) U3.D7(GND) U3.E3(GND) U3.E9(VOSNS0-) U3.F3(GND) U3.F10(GND) U3.G3(GND) U3.G10(GND) U3.G11(GND) U3.G12(GND) U3.H3(GND) U3.H10(GND) U3.J4(GND) U3.J10(GND) U3.K4(GND) U3.K7(GND) U3.K8(GND) U3.K9(GND) U3.L4(GND) U3.L5(GND) U3.L6(GND) U3.L7(GND) U3.L8(GND) U3.L9(GND) U3.M4(GND) U3.M6(GND) U3.M7(GND) U3.M8(GND) U3.M9(GND) U3.M10(GND) U4.2(GND) U5.A4(GND) U5.A6(GND) U5.A7(GND) U5.A8(GND) U5.A9(GND) U5.A10(GND) U5.B4(GND) U5.B5(GND) U5.B6(GND) U5.B7(GND) U5.B8(GND) U5.B9(GND) U5.C4(GND) U5.C6(GND) U5.C7(GND) U5.C8(GND) U5.C9(GND) U5.D4(GND) U5.D7(GND) U5.E3(GND) U5.E9(VOSNS0-) U5.F3(GND) U5.F10(GND) U5.G3(GND) U5.G10(GND) U5.G11(GND) U5.G12(GND) U5.H3(GND) U5.H10(GND) U5.J4(GND) U5.J10(GND) U5.K4(GND) U5.K7(GND) U5.K8(GND) U5.K9(GND) U5.L4(GND) U5.L5(GND) U5.L6(GND) U5.L7(GND) U5.L8(GND) U5.L9(GND) U5.M4(GND) U5.M6(GND) U5.M7(GND) U5.M8(GND) U5.M9(GND) U5.M10(GND) U6.2(GND) U7.A6(GND) U7.A7(GND) U7.B6(GND) U7.B7(GND) U7.D1(GND) U7.D2(GND) U7.D3(GND) U7.D4(GND) U7.D9(GND) U7.D10(GND) U7.D11(GND) U7.D12(GND) U7.E1(GND) U7.E2(GND) U7.E3(GND) U7.E4(GND) U7.E9(DIFFN) U7.E10(GND) U7.E11(GND) U7.E12(GND) U7.F1(GND) U7.F2(GND) U7.F3(GND) U7.F10(GND) U7.F11(GND) U7.F12(GND) U7.G1(GND) U7.G3(GND) U7.G10(GND) U7.G12(GND) U7.H1(GND) U7.H2(GND) U7.H3(GND) U7.H4(GND) U7.H5(GND) U7.H6(GND) U7.H7(GND) U7.H9(GND) U7.H10(GND) U7.H11(GND) U7.H12(GND) U7.J1(GND) U7.J5(GND) U7.J8(GND) U7.J12(GND) U7.K1(GND) U7.K5(GND) U7.K6(GND) U7.K7(GND) U7.K8(GND) U7.K12(GND) U7.L1(GND) U7.L12(GND) U7.M1(GND) U7.M12(GND) U8.19(GND) U8.20(GND) U8.21(GND) U8.22(CONTROL2) U8.23(CONTROL3) U8.27(TSENSE2) U8.28(WP) U8.34(TSENSE3) U8.35(ASEL0) U8.37(GND) U8.39(GND) U8.45(ISENSEP2) U8.46(ISENSEM2) U8.47(ISENSEP3) U8.48(ISENSEM3) U8.49(VSENSEP3) U8.50(VSENSEM3) U8.61(VSENSEP2) U8.62(VSENSEM2) U8.65(GND) U9.4(GND) U10.1(A0) U10.2(A1) U10.3(A2) U10.4(VSS) U10.7(WP) U11.17(GND) U11.21(GND) U12.2(GND) U13.2(NC) U13.5(GND) U13.17(GND)
GND_SIGNAL: C2.2 C3.2 C6.2 C10.2 C11.2 C13.2 C16.2 C17.2 C24.2 C25.2 C26.2 C32.2 C34.2 C35.2 Q3.2(S) R1.2 R15.2 R17.1 R19.1 R20.1 R22.1 R23.1 R24.1 R25.1 R29.2 R35.2 R36.1 R39.1 R40.1 R42.1 R43.1 R44.1 R45.1 R52.2 R54.1 R56.1 R57.1 R59.1 R60.1 R61.1 R62.1 R74.1 R81.1 R88.1 R94.1 U1.F5(SGND) U1.F6(SGND) U1.G5(SGND) U1.G6(SGND) U3.F7(SGND) U3.F8(SGND) U3.G7(SGND) U3.G8(SGND) U5.F7(SGND) U5.F8(SGND) U5.G7(SGND) U5.G8(SGND) U7.C7(SGND) U7.D6(SGND) U7.F6(SGND) U7.F7(SGND) U7.G6(SGND) U7.G7(SGND)
SVIN: C4.1 Q1.3(D) U1.F9(VINL) U3.F11(SVIN) U3.F12(SVIN) U5.F11(SVIN) U5.F12(SVIN)
VDD33_2974: C46.1 D11.1(CATHODE) Q10.2(S) U8.11(VDD33) U8.12(VDD33)
VDD33_4675: C53.1 D8.1(CATHODE) Q7.2(S) R7.1 R8.1 R9.1 R10.1 R11.1 R12.1 R13.1 R14.1 R99.1 R100.1 R101.1 U1.J5(VDD33) U9.8(VCC)
VDD33_4676: D9.1(CATHODE) P9.1(TP) Q8.2(S) R125.1 U3.J7(VDD33)
VDD33_4677: D10.1(CATHODE) P17.1(TP) Q9.2(S) R127.1 U5.J7(VDD33)
VIN: C45.1 C54.1 CIN1.1 CIN2.1 CIN3.1 CIN4.1 CIN5.1 CIN6.1 CIN7.1 CIN8.1 CIN9.1 CIN10.1 E1.1(TP) J2.1(VIN) J4.1(TP) Q1.2(S) R5.2 R6.1 R33.1 R50.1 R68.2 R86.2 R102.2 R108.1 R129.1 R130.2 U1.A9(VINH0) U1.B9(VINH0) U1.C9(VINH0) U1.D9(VINH0) U1.J9(VINH1) U1.K9(VINH1) U1.L9(VINH1) U1.M9(VINH1) U3.A11(VIN0) U3.A12(VIN0) U3.B11(VIN0) U3.B12(VIN0) U3.C11(VIN0) U3.C12(VIN0) U3.D11(VIN0) U3.D12(VIN0) U3.E12(VIN0) U3.H12(VIN1) U3.J11(VIN1) U3.J12(VIN1) U3.K11(VIN1) U3.K12(VIN1) U3.L11(VIN1) U3.L12(VIN1) U3.M11(VIN1) U3.M12(VIN1) U5.A11(VIN0) U5.A12(VIN0) U5.B11(VIN0) U5.B12(VIN0) U5.C11(VIN0) U5.C12(VIN0) U5.D11(VIN0) U5.D12(VIN0) U5.E12(VIN0) U5.H12(VIN1) U5.J11(VIN1) U5.J12(VIN1) U5.K11(VIN1) U5.K12(VIN1) U5.L11(VIN1) U5.L12(VIN1) U5.M11(VIN1) U5.M12(VIN1) U7.J2(VIN) U7.J3(VIN) U7.J4(VIN) U7.J9(VIN) U7.J10(VIN) U7.J11(VIN) U7.K2(VIN) U7.K3(VIN) U7.K4(VIN) U7.K9(VIN) U7.K10(VIN) U7.K11(VIN) U7.L2(VIN) U7.L3(VIN) U7.L4(VIN) U7.L5(VIN) U7.L6(VIN) U7.L7(VIN) U7.L8(VIN) U7.L9(VIN) U7.L10(VIN) U7.L11(VIN) U7.M2(VIN) U7.M3(VIN) U7.M4(VIN) U7.M5(VIN) U7.M6(VIN) U7.M7(VIN) U7.M8(VIN) U7.M9(VIN) U7.M10(VIN) U7.M11(VIN) U8.10(VPWR) U13.10(~{SHDN2}) U13.11(VIN2) U13.12(VIN2) U13.13(VIN1) U13.14(VIN1) U13.15(~{SHDN1})
ALERTB: E18.1(A) J14.6(ALERTB) J15.3(ALERTB) J16.3(ALERTB) R9.2 U1.E3(~{ALERT}) U3.E5(~{ALERT}) U5.E5(~{ALERT}) U8.31(ALERTB) U12.1(1A)
AUX3V3: E16.1(A) J14.5(LGKPWR) Q7.3(D) Q8.3(D) Q9.3(D) Q10.3(D)
AUX3V4: D8.2(ANODE) D9.2(ANODE) D10.2(ANODE) D11.2(ANODE) E14.1(A) J13.4(AUX3V4)
AUXP: C50.1 E15.1(A) J14.1(AUXP) J15.8(AUXP) J16.8(AUXP) R106.1 R107.1 R129.2 U10.8(VCC)
COMP4a: C17.1 C18.1 R48.2 R53.1 U5.E8(COMP0a) U5.H8(COMP1a)
CREATE_FAULT: Q6.1(G) R112.1 R117.1 SW3.2
CTRL: E17.1(A) J15.2(CTRL) J16.2(CTRL) R13.2 R103.1 U1.F3(RUN0) U1.F4(RUN1) U3.F5(RUN0) U3.F6(RUN1) U5.F5(RUN0) U5.F6(RUN1) U8.32(CONTROL0) U8.33(CONTROL1)
EESCL: J14.11(AUXSCL) R106.2 U10.6(SCL)
EESDA: J14.12(AUXSDA) R107.2 U10.5(SDA)
FAULTB: E13.1(A) J15.1(FAULTB) J16.1(FAULTB) R12.2 U1.E2(~{GPIO0}) U1.F2(~{GPIO1}) U3.E4(~{GPIO0}) U3.F4(~{GPIO1}) U5.E4(~{GPIO0}) U5.F4(~{GPIO1}) U8.25(FAULTB0) U8.26(FAULTB1) U12.3(2A)
INTVCC_4620A: C21.1 R64.2 R89.2 R122.2 R123.2 U7.H8(INTVCC)
ISENSEM0: C41.2 R92.2 U8.42(ISENSEM0)
ISENSEM1: C28.2 R73.2 U8.44(ISENSEM1)
ISENSEP0: C43.1 R95.2 U8.41(ISENSEP0)
ISENSEP1: C30.1 R79.2 U8.43(ISENSEP1)
PGOOD0: D2.2(K) U2.6(OUTB)
PGOOD1: D1.2(K) U2.1(OUTA)
PGOOD2: D4.2(K) U4.6(OUTB)
PGOOD3: D3.2(K) U4.1(OUTA)
PGOOD4: D5.2(K) U6.1(OUTA)
PGOOD5: Q11.1(G) R123.1 U7.G8(PGOOD2)
PGOOD6: Q12.1(G) R122.1 U7.G9(PGOOD1)
RESETB: C51.1 E20.1(A) J15.7(RESETB) J16.7(RESETB) Q2.1(G) R14.2 SW2.1 U8.24(WDI/RESETB)
RUN5: U7.F5(RUN1) U8.3(VOUT_EN0)
RUN6: U7.F9(RUN2) U8.4(VOUT_EN1)
SCL: E21.1(A) R10.2 U1.E4(SCL) U3.E6(SCL) U5.E6(SCL) U8.30(SCL) U9.2(SCLOUT)
SCL_IN: J13.3(SCL) J14.4(SCL) J15.6(SCL) J16.6(SCL) R100.2 U9.3(SCLIN) U11.19(SCL)
SDA: E22.1(A) R11.2 U1.D4(SDA) U3.D6(SDA) U5.D6(SDA) U8.29(SDA) U9.7(SDAOUT)
SDA_IN: J13.1(SDA) J14.2(SDA) J15.4(SDA) J16.4(SDA) R99.2 U9.6(SDAIN) U11.20(SDA)
SHARE_CLK: E19.1(A) J15.5(SHARE_CLK) J16.5(SHARE_CLK) R8.2 U1.H5(SHARE_CLK) U3.H7(SHARE_CLK) U5.H7(SHARE_CLK) U8.18(SHARE_CLK)
SYNC: E4.1(A) R7.2 R124.1 R126.1 R128.2 U1.E5(SYNC)
UNUSED1: J15.9(UNUSED) J16.9(UNUSED)
UNUSED2: J15.10(UNUSED) J16.10(UNUSED)
VDAC0: R82.2 U8.53(VDAC0)
VDAC1: R71.1 U8.54(VDAC1)
VOUT0: COUT1.1 COUT2.1 COUT3.1 COUT4.1 J1.1(TP) R2.1 R3.2 U1.J1(VOUT1) U1.K1(VOUT1) U1.L1(VOUT1) U1.M1(VOUT1)
VOUT0_SNS: C3.1 E2.1(TP) R2.2 U1.H7(VOSNS1) U2.4(INB)
VOUT1: COUT5.1 COUT6.1 COUT7.1 COUT8.1 J5.1(TP) R18.2 R21.2 U1.A1(VOUT0) U1.B1(VOUT0) U1.C1(VOUT0) U1.D1(VOUT0)
VOUT1_SNS: C7.1 E5.1(TP) R18.1 U1.D7(VOSNS0+) U2.3(INA)
VOUT2: COUT9.1 COUT10.1 COUT11.1 COUT12.1 J7.1(TP) R28.2 R32.1 U3.J1(VOUT1) U3.J2(VOUT1) U3.J3(VOUT1) U3.K1(VOUT1) U3.K2(VOUT1) U3.K3(VOUT1) U3.L1(VOUT1) U3.L2(VOUT1) U3.L3(VOUT1) U3.M1(VOUT1) U3.M2(VOUT1) U3.M3(VOUT1)
VOUT2_SNS: C11.1 E7.1(TP) R32.2 U3.H9(VOSNS1) U4.4(INB)
VOUT3: COUT13.1 COUT14.1 COUT15.1 COUT16.1 J8.1(TP) R38.2 R41.2 U3.A1(VOUT0) U3.A2(VOUT0) U3.A3(VOUT0) U3.B1(VOUT0) U3.B2(VOUT0) U3.B3(VOUT0) U3.C1(VOUT0) U3.C2(VOUT0) U3.C3(VOUT0) U3.D1(VOUT0) U3.D2(VOUT0) U3.D3(VOUT0)
VOUT3_SNS: C14.1 E8.1(TP) R38.1 U3.D9(VOSNS0+) U4.3(INA)
VOUT4: C16.1 COUT17.1 COUT18.1 COUT20.1 COUT21.1 COUT22.1 COUT23.1 COUT33.1 COUT34.1 J9.1(TP) R55.2 R58.2 R131.2 U5.A1(VOUT0) U5.A2(VOUT0) U5.A3(VOUT0) U5.B1(VOUT0) U5.B2(VOUT0) U5.B3(VOUT0) U5.C1(VOUT0) U5.C2(VOUT0) U5.C3(VOUT0) U5.D1(VOUT0) U5.D2(VOUT0) U5.D3(VOUT0) U5.H9(VOSNS1) U5.J1(VOUT1) U5.J2(VOUT1) U5.J3(VOUT1) U5.K1(VOUT1) U5.K2(VOUT1) U5.K3(VOUT1) U5.L1(VOUT1) U5.L2(VOUT1) U5.L3(VOUT1) U5.M1(VOUT1) U5.M2(VOUT1) U5.M3(VOUT1)
VOUT4_SNS: C19.1 E9.1(TP) R55.1 U5.D9(VOSNS0+) U6.3(INA)
VOUT5+: COUT25.1 COUT26.1 COUT27.1 COUT28.1 J11.1 R65.2 R66.1 R72.1 U7.A8(VOUT2) U7.A9(VOUT2) U7.A10(VOUT2) U7.A11(VOUT2) U7.A12(VOUT2) U7.B8(VOUT2) U7.B9(VOUT2) U7.B10(VOUT2) U7.B11(VOUT2) U7.B12(VOUT2) U7.C9(VOUT2) U7.C10(VOUT2) U7.C11(VOUT2) U7.C12(VOUT2)
VOUT6: COUT29.1 COUT30.1 COUT31.1 COUT32.1 J12.1 R76.2 R80.2 R93.1 U7.A1(VOUT1) U7.A2(VOUT1) U7.A3(VOUT1) U7.A4(VOUT1) U7.A5(VOUT1) U7.B1(VOUT1) U7.B2(VOUT1) U7.B3(VOUT1) U7.B4(VOUT1) U7.B5(VOUT1) U7.C1(VOUT1) U7.C2(VOUT1) U7.C3(VOUT1) U7.C4(VOUT1)
VOUT6+: C31.1 E12.1 R75.2 R76.1 R85.1 U7.E8(DIFFP)
VSENSEM0: C38.2 R87.2 U8.2(VSENSEM0)
VSENSEM1: C23.2 R70.2 U8.64(VSENSEM1)
VSENSEP0: C36.1 R85.2 U8.1(VSENSEP0)
VSENSEP1: C22.1 R69.2 U8.63(VSENSEP1)
N17002004: C5.2 R15.1
N17002011: C5.1 C6.1 R16.1 U1.E6(COMP0a)
N17134921: P4.1(TP) U1.D8(VORB0+)
N17135374: P5.1(TP) U1.E8(VORB0-)
N17138086: R16.2 U1.D6(COMP0b)
N17139451: U1.C3(TSNS0) U1.D3(TSNS0)
N17152710: C1.1 C2.1 R4.2 U1.H6(COMP1a)
N17154876: R4.1 U1.J6(COMP1b)
N17160063: P2.1(TP) U1.J7(VORB1)
N17166430: P1.1(TP) U1.L8(SW1)
N17174598: R6.2 U1.F7(INTVCC) U1.G7(INTVCC)
N17222714: R19.2 U1.G2(ASEL)
N17223298: R20.2 U1.H2(FREQ_CFG)
N17223884: R22.2 U1.G3(VOUT0_CFG)
N17224472: R23.2 U1.H3(VTRIM0_CFG)
N17225062: R24.2 U1.G4(VOUT1_CFG)
N17225654: R25.2 U1.H4(VTRIM1_CFG)
N17491667: R17.2 U1.K4(WP)
N17988510: C1.2 R1.1
N18073508: P3.1(TP) U1.B8(SW0)
N18350811: U1.J3(TSNS1a) U1.K3(TSNS1b)
N18401773: R37.2 U3.D8(COMP0b)
N18401829: C12.1 C13.1 R37.1 U3.E8(COMP0a)
N18401857: D15.1(K) R33.2 U3.F9(INTVCC) U3.G9(INTVCC)
N18401860: U3.H1(ISNS1b+) U3.H2(ISNS1a+)
N18401889: U3.C5(TSNS0b) U3.D5(TSNS0a)
N18401891: U3.G1(ISNS1b-) U3.G2(ISNS1a-)
N18401899: C9.1 C10.1 R31.2 U3.H8(COMP1a)
N18401954: U3.F1(ISNS0b+) U3.F2(ISNS0a+)
N18402011: U3.E1(ISNS0b-) U3.E2(ISNS0a-)
N18402216: P7.1(TP) U3.L10(SW1)
N18402278: P10.1(TP) U3.B10(SW0)
N18402299: R34.1 U3.A5(SNUB0)
N18402335: R31.1 U3.J8(COMP1b)
N18402362: R36.2 U3.K6(WP)
N18402548: R30.1 U3.M5(SNUB1)
N18402735: C12.2 R35.1
N18402802: R39.2 U3.G4(ASEL)
N18402868: R40.2 U3.H4(FSWPHCFG)
N18402931: R42.2 U3.G5(VOUT0CFG)
N18402979: R43.2 U3.H5(VTRIM0CFG)
N18403016: P8.1(TP) U3.J9(VORB1)
N18403018: C9.2 R29.1
N18403042: R44.2 U3.G6(VOUT1CFG)
N18403097: P11.1(TP) U3.D10(VORB0+)
N18403121: R45.2 U3.H6(VTRIM1CFG)
N18403145: P12.1(TP) U3.E10(VORB0-)
N18408403: U3.J5(TSNS1a) U3.K5(TSNS1b)
N18481195: U5.J5(TSNS1A) U5.K5(TSNS1B)
N18481203: R53.2 U5.D8(COMP0b)
N18481233: R49.1 U5.M5(SNUB1)
N18481295: R50.2 U5.F9(INTVCC) U5.G9(INTVCC)
N18481341: U5.C5(TSNS0B) U5.D5(TSNS0A)
N18481666: P14.1(TP) U5.L10(SW1)
N18481746: P16.1(TP) U5.B10(SW0)
N18481789: R48.1 U5.J8(COMP1b)
N18481818: R54.2 U5.K6(WP)
N18482224: C18.2 R52.1
N18482291: R56.2 U5.G4(ASEL)
N18482354: R57.2 U5.H4(FSWPHCFG)
N18482417: R59.2 U5.G5(VOUT0CFG)
N18482462: R60.2 U5.H5(VTRIM0CFG)
N18482499: P15.1(TP) U5.J9(VORB1)
N18482525: R61.2 U5.G6(VOUT1CFG)
N18482572: P18.1(TP) U5.D10(VORB0+)
N18482596: R62.2 U5.H6(VTRIM1CFG)
N18482628: P19.1(TP) U5.E10(VORB0-)
N18482723: R51.2 U5.A5(SNUB0)
N18550586: C31.2 C34.1 R81.2 R82.1 U7.D5(VFB1)
N18550705: R75.1 R77.2 U7.C5(VOUT1S)
N18550882: R68.1 U7.J6(TEMP)
N18550981: C32.1 U7.E7(COMP2)
N18551007: C26.1 R71.2 R74.2 U7.D7(VFB2)
N18551138: R77.1 U7.F8(DIFFOUT)
N18551304: E11.1 R66.2 R69.1 U7.C8(VOUT2S)
N18551433: C35.1 Q6.3(D) U7.E6(COMP1)
N18551565: C25.1 U7.E5(TRACK1)
N18551611: R88.2 U7.C6(FSET)
N18552284: C24.1 U7.D8(TRACK2)
N18552290: P21.1(TP) R78.1 U7.G11(SW2)
N18608729: Q3.3(D) R64.1 R67.2
N18624382: R67.1 U7.F4(MODE-PLLIN)
N18735827: R89.1 R94.2 U7.G4(PHASMD)
N18820115: C47.1 U8.13(VDD25(OUT)) U8.14(VDD25(IN))
N18988388: C33.1 C59.1 Q4.2(E) U8.16(TSENSE1)
N19006674: C29.1 R78.2 R79.1
N19006678: C27.2 R72.2 R73.1
N19073935: C44.1 R95.1 R96.2
N19079761: C42.2 R92.1 R93.2
N19080542: P22.1(TP) R96.1 U7.G2(SW1)
N19115411: C39.1 C60.1 Q5.2(E) U8.15(TSENSE0)
N19118752: C37.1 R86.1 U8.9(VIN_SNS)
N19158995: C40.1 U8.40(REFM)
N19159782: C40.2 U8.38(REFP)
N19405372: Q1.1(G) Q2.3(D) R5.1
N19489447: D1.1(A) R26.2
N19489944: D2.1(A) R27.2
N19492327: D3.1(A) R46.2
N19492331: D4.1(A) R47.2
N19504016: D5.1(A) R63.2
N19513340: D6.1(A) R97.2
N19513342: D7.1(A) R98.2
N19566666: J15.13(12V) J15.14(12V) J16.13(12V) J16.14(12V) R108.2
N19587334: R103.2 R105.2 SW1.1 SW1.2
N19587364: C49.1 R105.1
N19620899: R101.2 R114.2 U9.1(ENABLE) U11.9(GP0)
N19694595: D12.1(A) R115.2
N19694984: D12.2(K) U12.6(1Y)
N19695770: D13.1(A) R116.2
N19696165: D13.2(K) U12.4(2Y)
N19703574: C58.2 U13.8(BYP2)
N19703602: R119.2 R121.1 U13.9(ADJ2)
N19703752: R118.2 R120.1 U13.16(ADJ1)
N19703766: C57.2 U13.1(BYP1)
N19744475: C52.1 R113.1 U11.4(~{RESET})
N19753965: R112.2 U11.16(GP7)
N19771669: R109.2 SW4.6 U11.3(A0)
N19772174: R110.2 SW4.5 U11.2(A1)
N19772681: R111.2 SW4.4 U11.1(A2)
N20298783: Q7.1(G) Q8.1(G) Q9.1(G) Q10.1(G) R102.1 R104.1
N20599878: D6.2(K) Q12.3(D)
N20607805: D7.2(K) Q11.3(D)
N20684449: R124.2 R125.2 U3.E7(SYNC)
N20693526: R126.2 R127.2 U5.E7(SYNC)
N20712025: Q3.1(G) R128.1
N20864818: D14.1(A) R130.1
N20959710: U5.E1(ISNS0a-) U5.E2(ISNS0b-)
N20961231: U5.F1(ISNS0b+) U5.F2(ISNS0a+)
N20965061: U5.G1(ISNS1b-) U5.G2(ISNS1a-)
N20966606: U5.H1(ISNS1b+) U5.H2(ISNS1a+)
N20974552: P13.1(TP) U3.J6(VDD25)
N20975706: P6.1(TP) U1.J4(VDD25)
N20976500: P20.1(TP) U5.J6(VDD25)

Not connected (* = marked no-connect by the designer): J14 7(GPIO_1) 8(OUTEN_0) 9(OUTEN_1); SW1 4 5 6; U3 C10(DNC) E11(DNC) H11(DNC) K10(DNC); U5 C10(NC) E11(NC) H11(NC) K10(NC); U6 4(INB) 6(OUTB); U7 G5(CLKOUT) J7(EXTVCC); U8 5(VOUT_EN2) 6(VOUT_EN3) 7(AUXFAULTB) 8(NC) 17(PWRGD) 36(ASEL1) 51(NC) 52(NC) 55(NC) 56(NC) 57(VDAC2) 58(VDAC3) 59(NC) 60(NC); U9 5(READY); U11 5(NC) 6(NC) 7(INT) 8(NC) 10(GP1) 11(GP2) 12(GP3) 13(GP4) 14(GP5) 15(GP6)

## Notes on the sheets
sheet 1
- 0.9V / 9A
- 1206
- 1206
- 1206
- 1206
- 0.035 VIA
- TESTPOINTS
- 4.5V - 15V
- 20V
- 20V
- 1210
- 1210
- 0.7V / 9A
- 1206
- 1206
- 1206
- 1206
- NOTE: UNLESS OTHERWISE SPECIFIED
- 1.  ALL RESISTORS ARE 0603.
       ALL CAPACITORS ARE 0603.
- WHEN VIN < 5.75V, SHORT INTVCC TO VIN WITH R6, R33, R50 = 0ohm.
  FOR LOW POWER DEMO ONLY, USE DC POWER JACK J20 TO PROVIDE 12V VIN;
  FOR FULL POWER DEMO, USE BANANA JACK J1 TO PROVIDE 12V VIN.
- LTM4620AEY+LTC2974CUP
sheet 2
- 1.5V / 13A
- 1206
- 1206
- 1206
- 1206
- 0.035 VIA
- 0805
- TESTPOINTS
- 1210
- 1210
- OPT
- 1.2V / 13A
- 1206
- 1206
- 1206
- 1206
- NOTE: UNLESS OTHERWISE SPECIFIED
- 1.  ALL RESISTORS ARE 0603.
       ALL CAPACITORS ARE 0603.
- LTM4620AEY+LTC2974CUP
sheet 3
- 1206
- 1206
- 1206
- 0.035 VIA
- TESTPOINTS
- 1210
- 1210
- 1.0V / 36A
- 1206
- 1206
- 1206
- 1206
- 1206
- LTM4620AEY+LTC2974CUP
sheet 4
- VOUT5
- 0.95V @ 12A
- 1206
- 1206
- 1206
- 1206
- VO5+
- 1210
- 1210
- VO6+
- VOUT6
- 0.85V @ 12A
- 1206
- 1206
- 1206
- 1206
- LTM4620AEY+LTC2974CUP
sheet 5
- TO DC2086A
- CONTROL
- ON
- TO DC1613A
- OFF
- 1206
- PSM STACKING CONNECTORS:
- J16, MALE, CONN  HEADER 14POS 2MM R/A GOLD, Molex Connector Corp. 87760-1416
- J15, FEMALE, CONN RECEPT 2MM DUAL R/A 14POS, Sullins Conn.
  NPPN072FJFN-RC
- 1206
- 1206
- LTM4620AEY+LTC2974CUP
